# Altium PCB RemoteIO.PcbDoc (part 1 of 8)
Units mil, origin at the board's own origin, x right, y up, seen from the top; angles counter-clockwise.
Board outline 7874.02 x 2362.2 mil, 6 copper layers (Top Layer, GND1, Layer 2, PWR, GND2, Bottom Layer), stack 60.956 mil thick; 655 components, 447 nets, 2607 pads, 1444 vias.
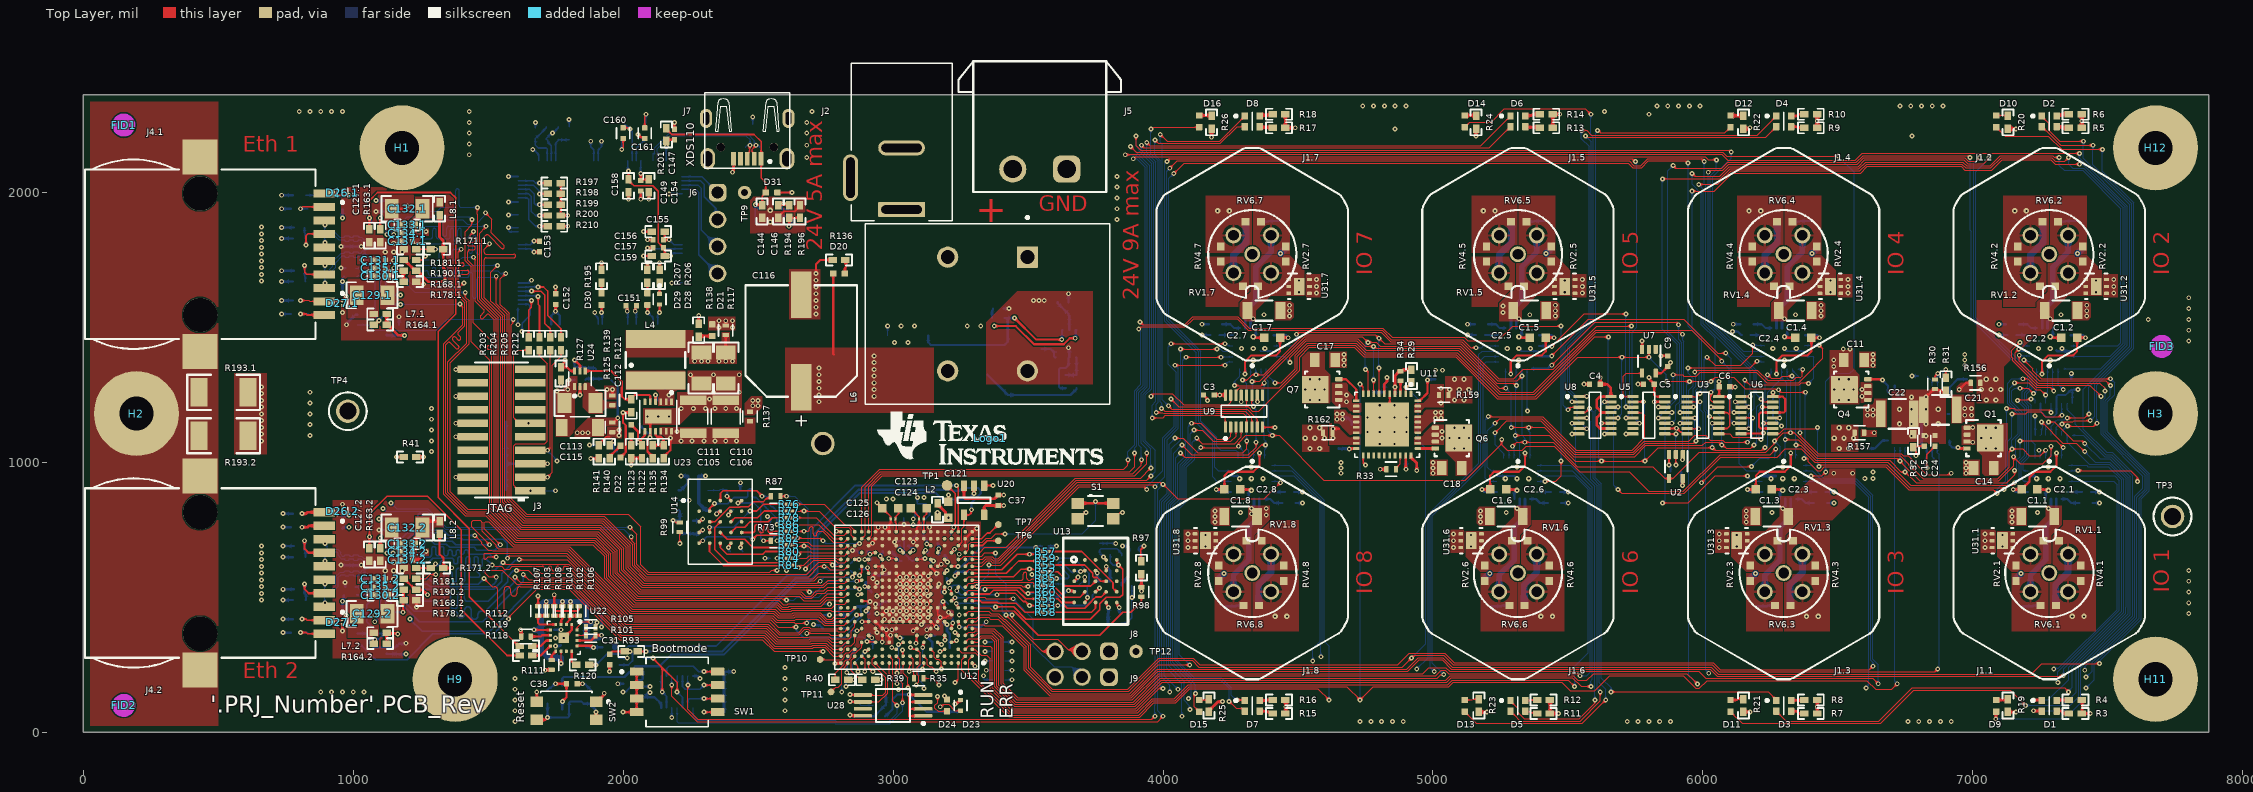
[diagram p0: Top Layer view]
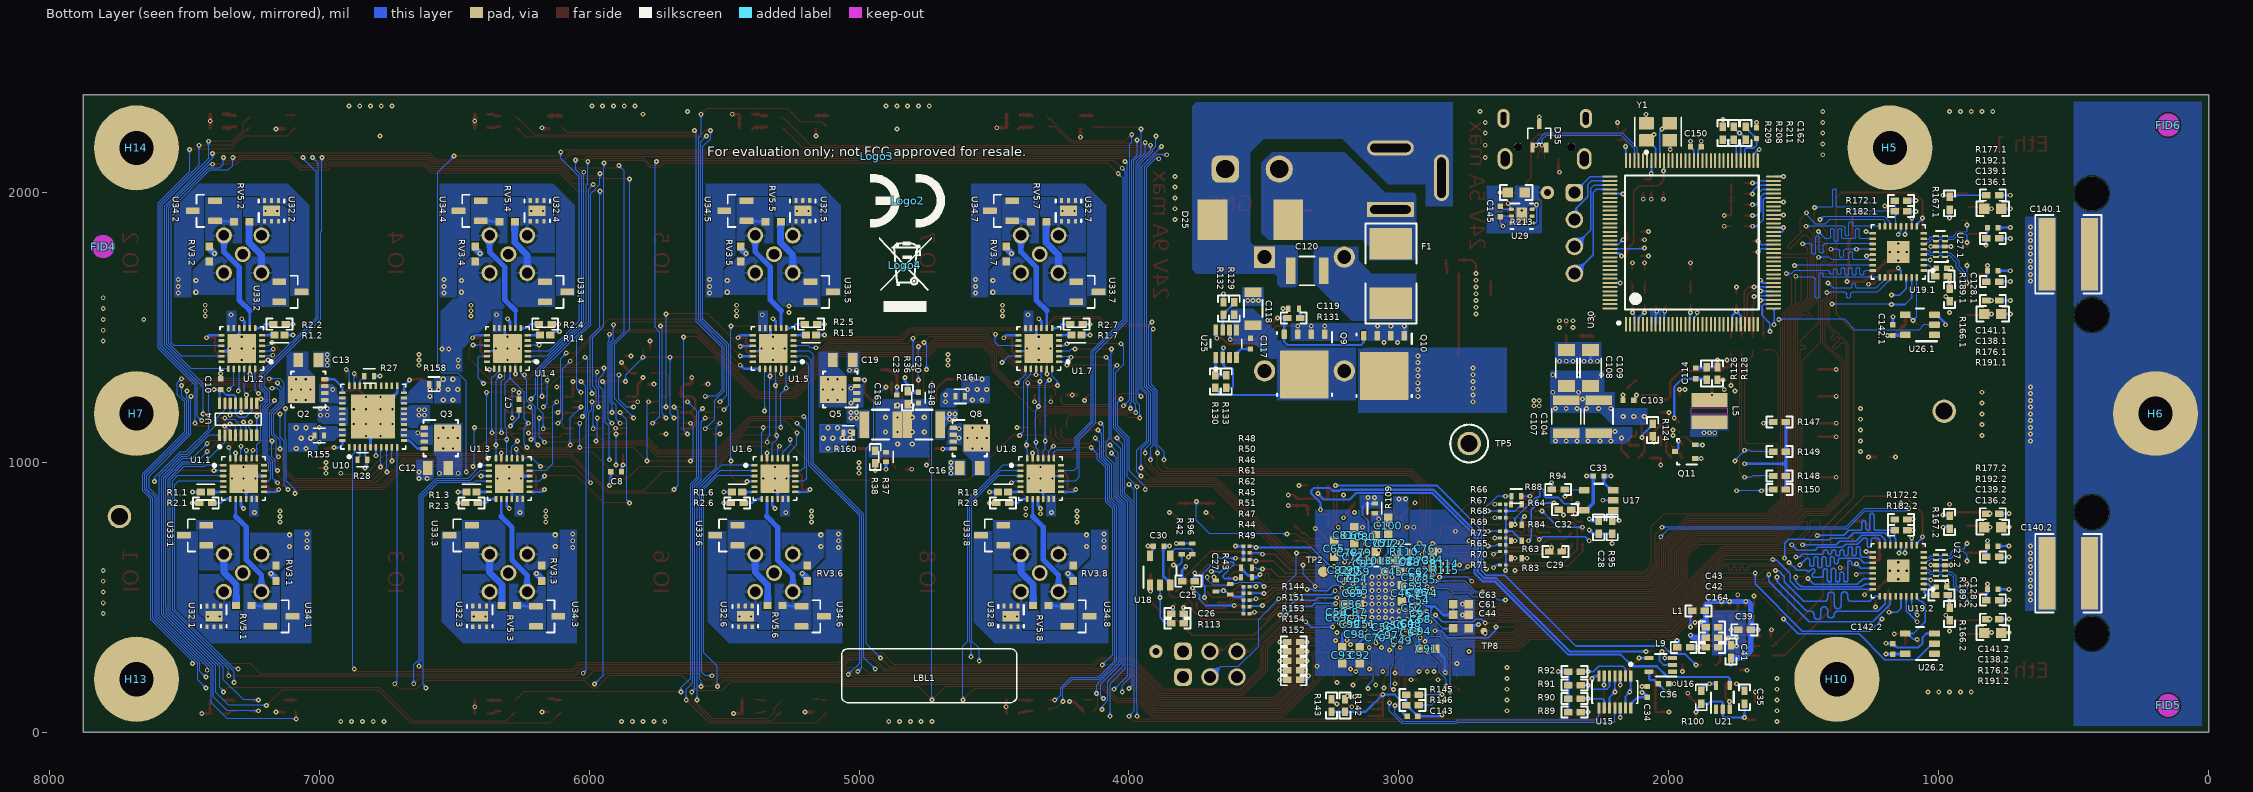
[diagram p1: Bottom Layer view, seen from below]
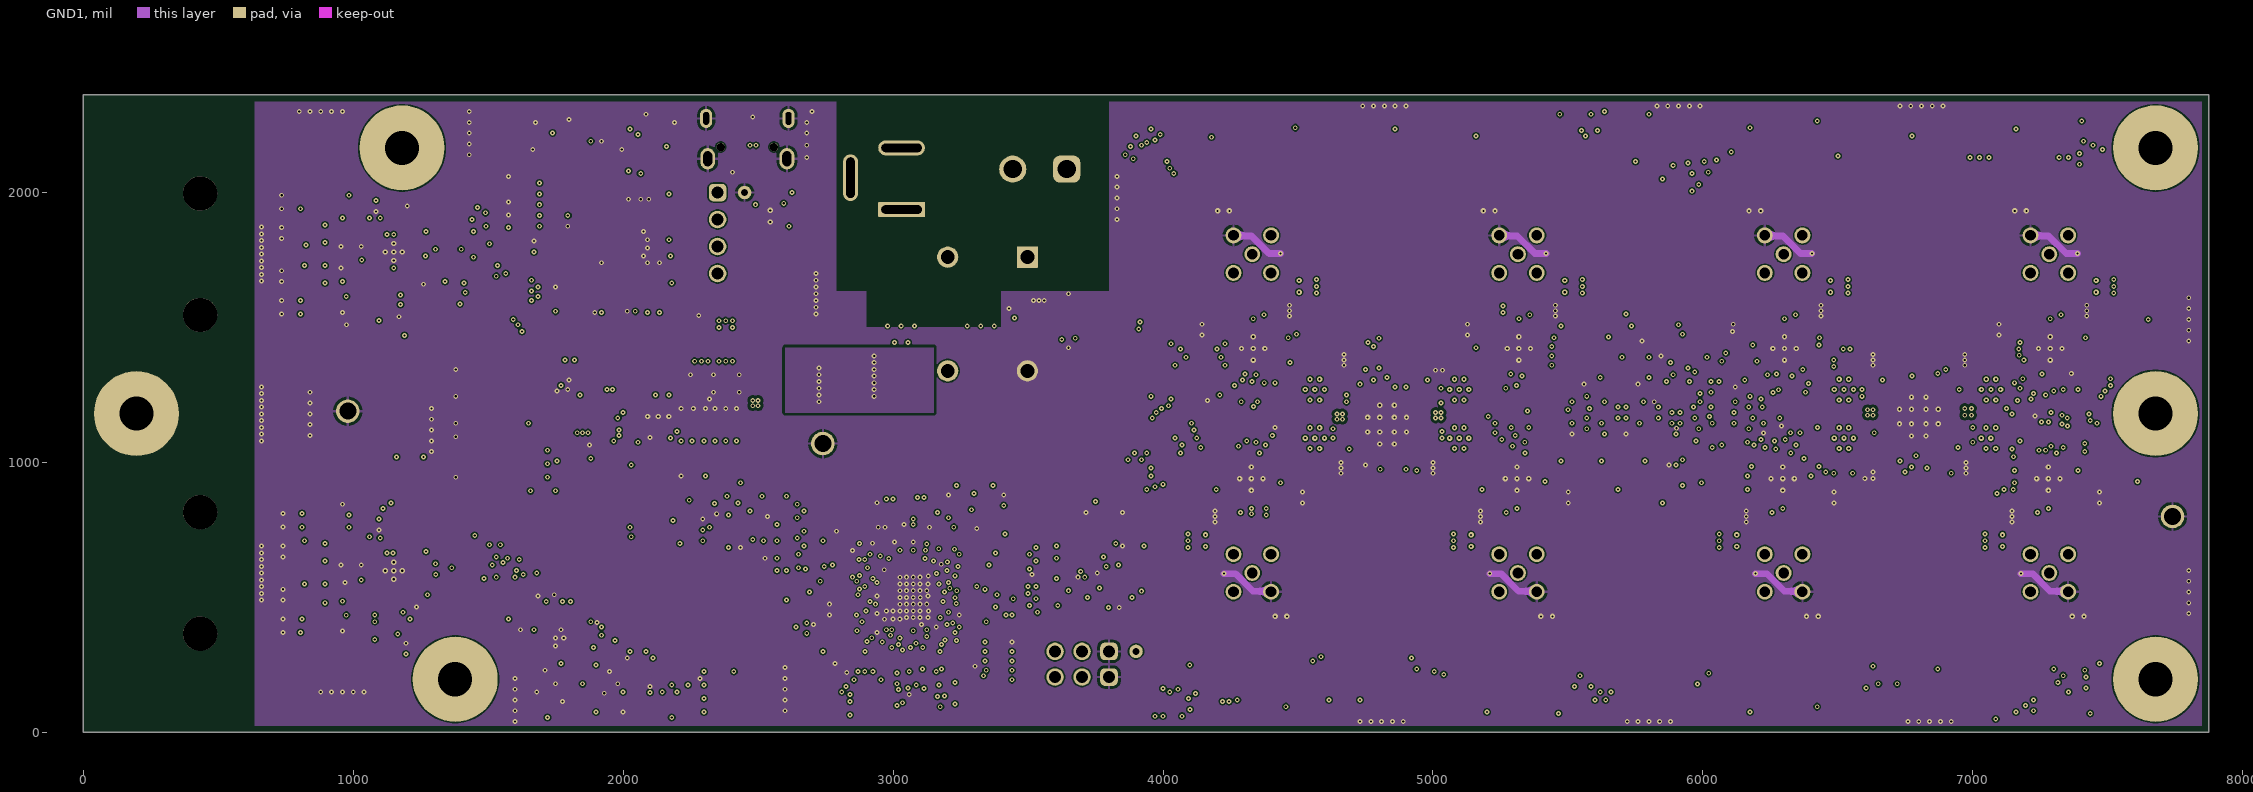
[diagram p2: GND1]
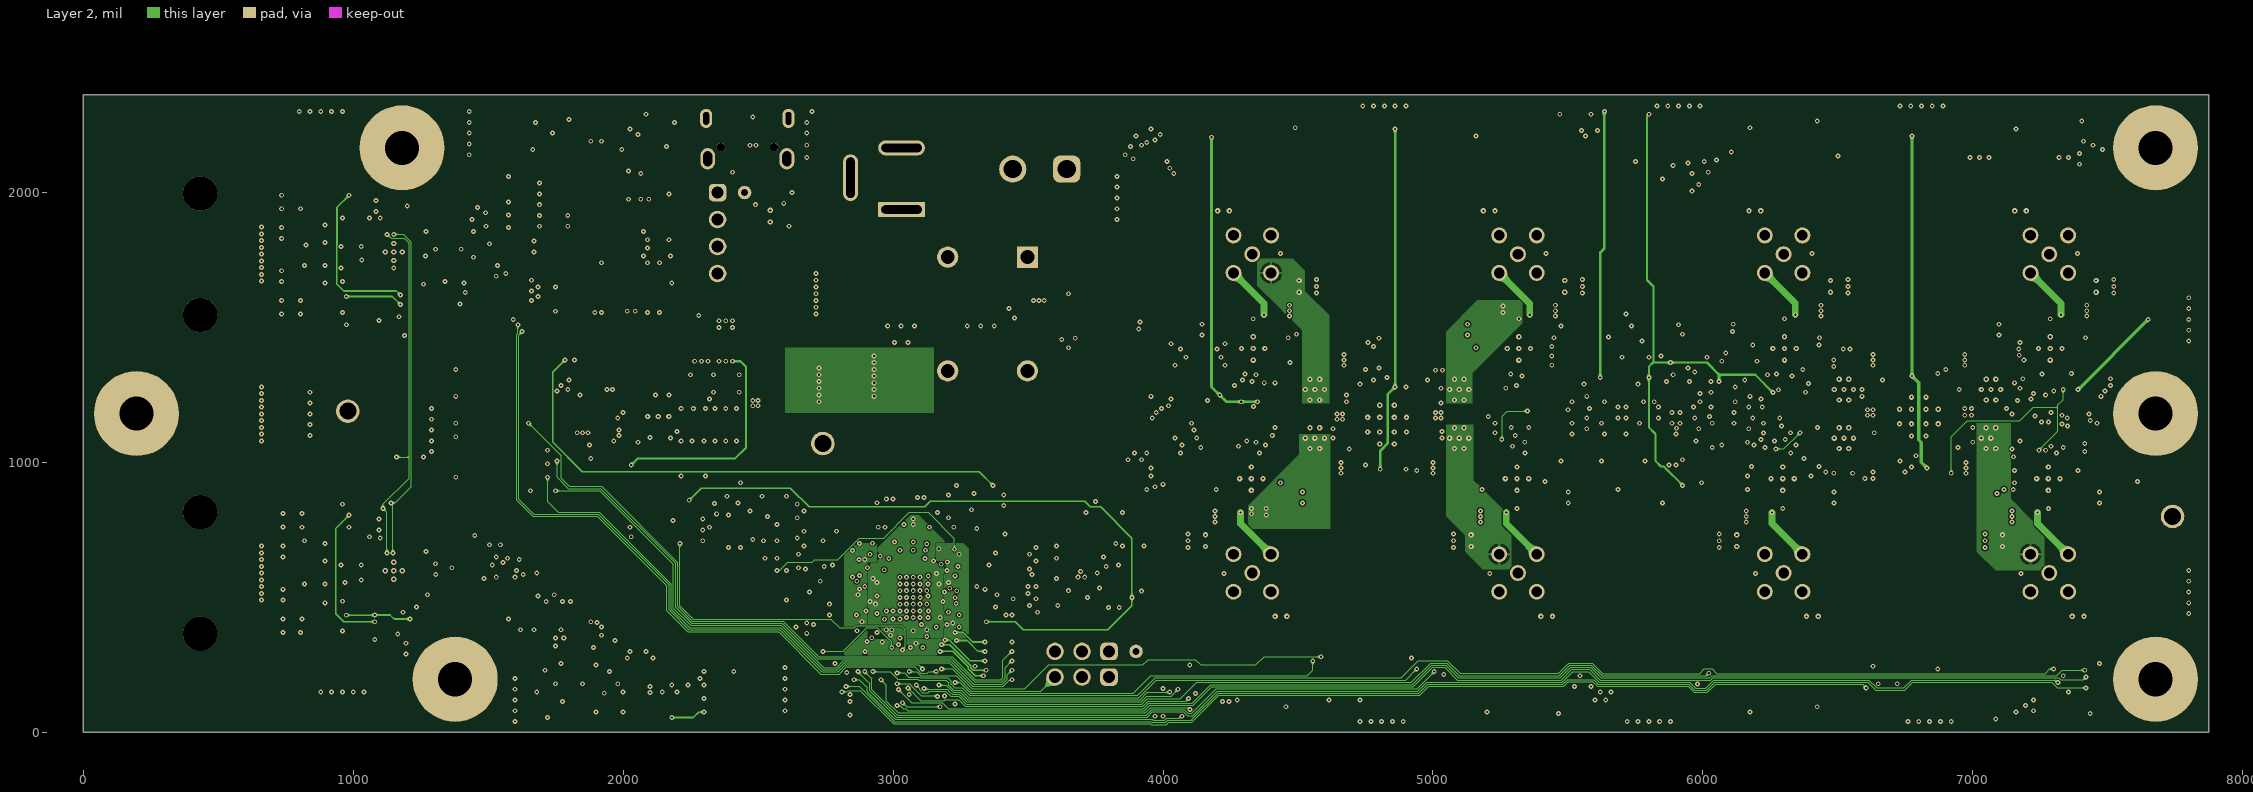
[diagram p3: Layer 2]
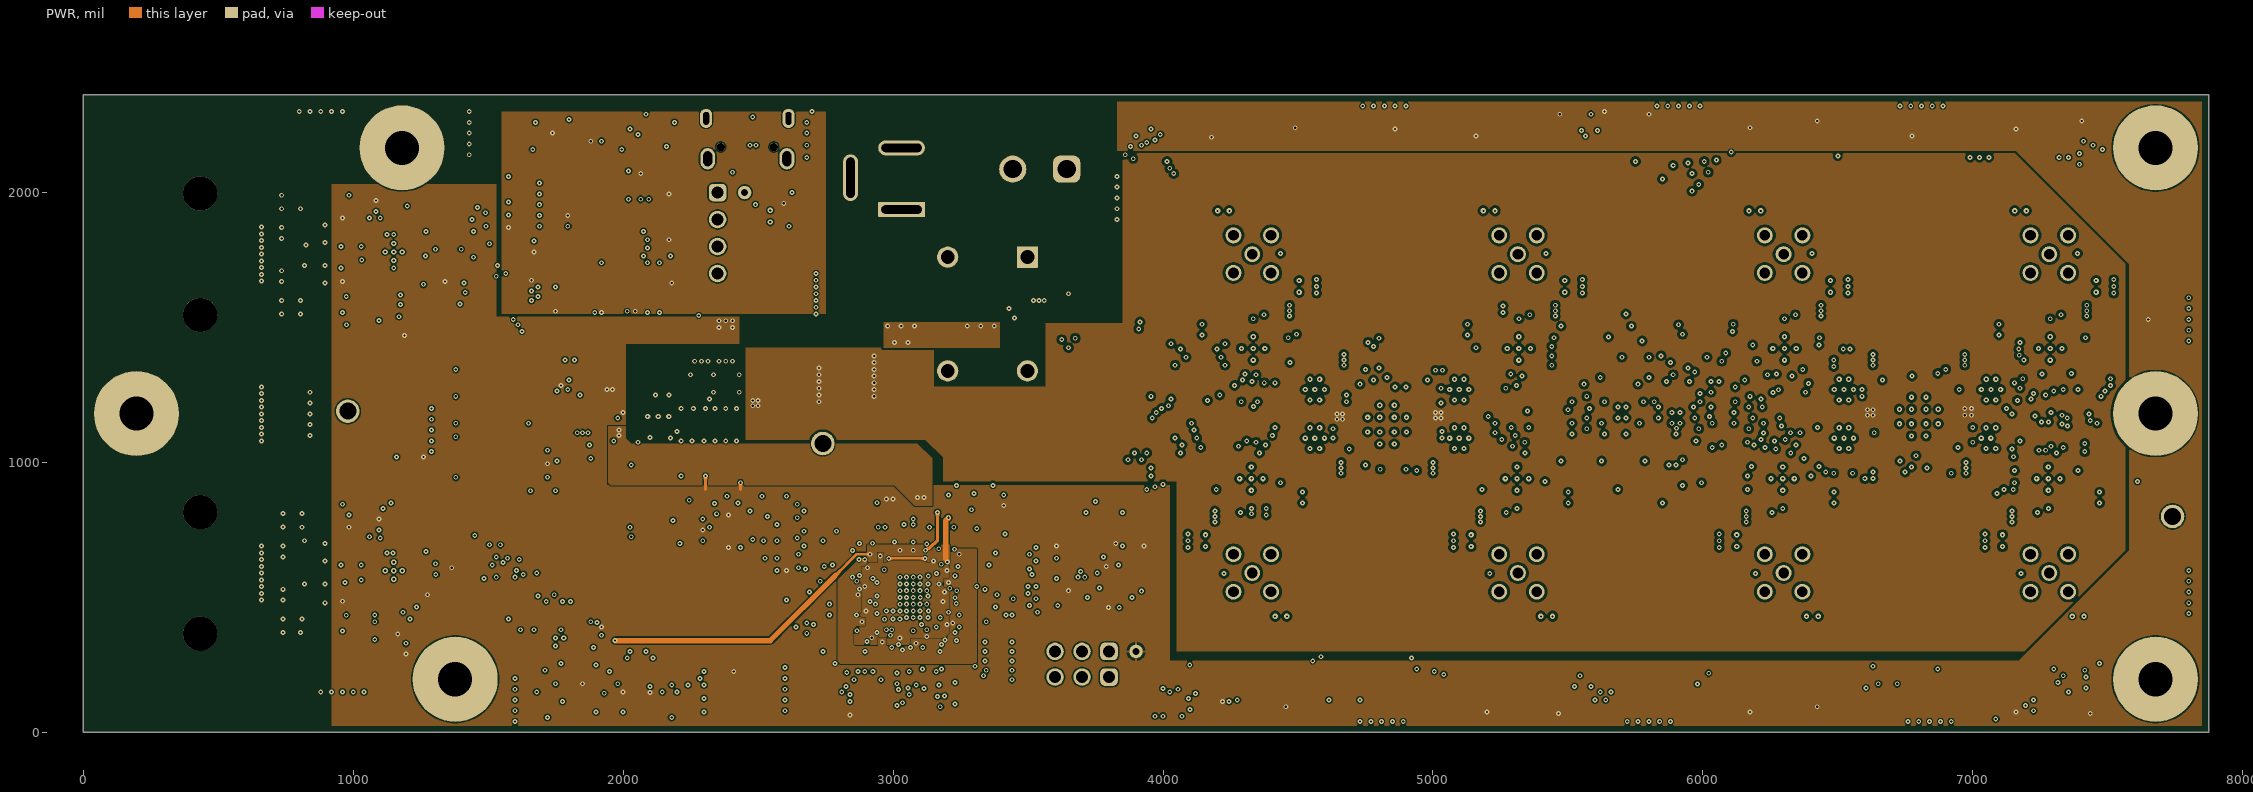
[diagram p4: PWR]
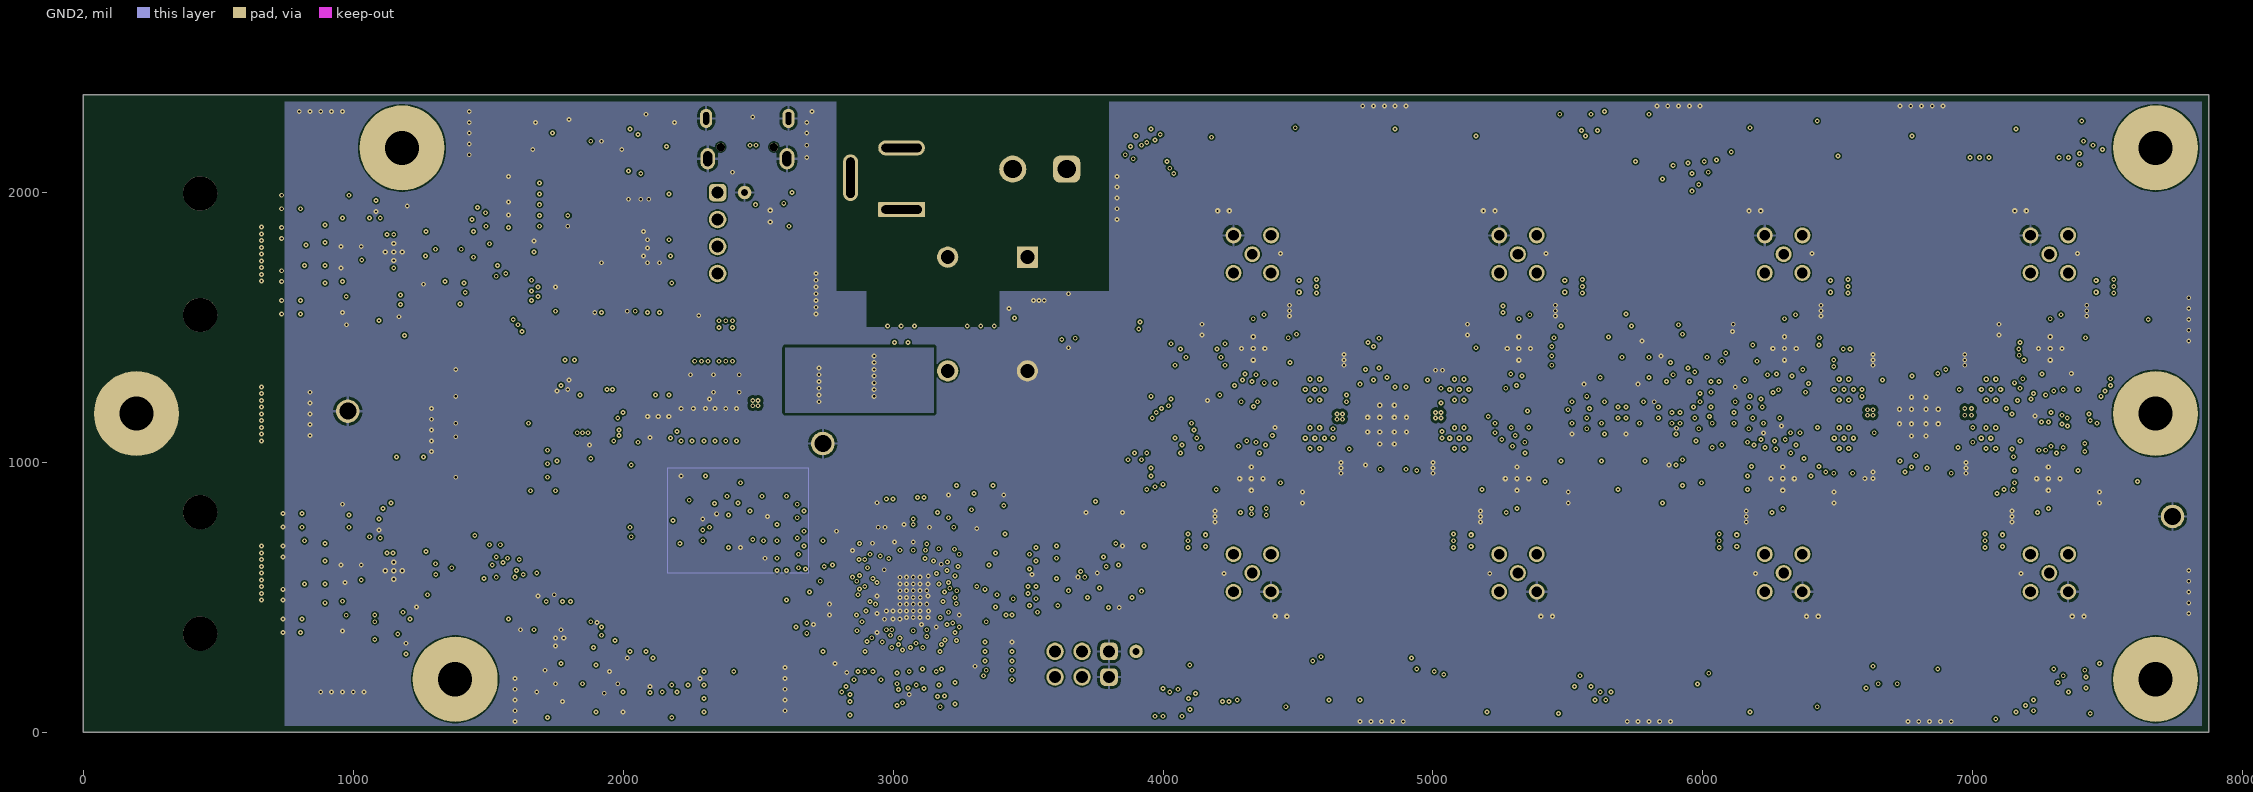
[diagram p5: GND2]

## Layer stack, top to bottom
Top Solder: solder mask 0.4, Solder Resist, Dk 3.5
Top Layer: signal copper 1.4
Dielectric 1: prepreg 3.91, PP-015, Dk 4.3
GND1: signal copper 0.689
Dielectric 2: core 21.65, Core-037, Dk 4.8
Layer 2: signal copper 0.689
Dielectric1: prepreg 4.28, PP-016, Dk 4.4
PWR: signal copper 0.689
Dielectric 3: core 21.65, Core-037, Dk 4.8
GND2: signal copper 0.689
Dielectric 4: prepreg 3.91, PP-015, Dk 4.3
Bottom Layer: signal copper 1.4
Bottom Solder: solder mask 0.4, Solder Resist, Dk 3.5

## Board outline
0,0 7874.02,0 7874.02,2362.2 0,2362.2

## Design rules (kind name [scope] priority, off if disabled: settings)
AcuteAngle [All] p1: minimum=4.50000000000000E+0001 checktracksonly=FALSE
AssemblyTestPointUsage [All] p1: valid=2
BoardOutlineClearance BoardOutlineClearance_MountingHoles [OnCopper and InComponentClass('Mounting Holes')] p1: gap=39.37 ignorepadtopadclearanceinfootprint=FALSE
BoardOutlineClearance BoardOutlineClearance_Poly [OnCopper and IsPoly] p2: gap=25 ignorepadtopadclearanceinfootprint=FALSE
BoardOutlineClearance [OnCopper and Not InComponentClass('Logo') and not InComponentClass('FiducialMark') and not InRegion(1000,500,4000,800) and not InPoly] p3: gap=20 ignorepadtopadclearanceinfootprint=FALSE
Clearance Clearance_24V [InNet('24V')] p1: gap=10 ignorepadtopadclearanceinfootprint=TRUE
Clearance Clearance_CPU [WithinRoom('CPU')] p2: gap=3.5 ignorepadtopadclearanceinfootprint=TRUE
Clearance Clearance_Keepouts [((IsTrack Or IsArc) And Not InPoly) And IsFree and IsKeepOut vs ((IsTrack Or IsArc) And Not InPoly) And IsFree and IsKeepOut] p3: gap=0 ignorepadtopadclearanceinfootprint=FALSE
Clearance Clearance_Poly [InPolygon] p4: gap=5 ignorepadtopadclearanceinfootprint=TRUE
Clearance Clearance_FiducialMark [IsKeepOut and InComponentClass('FiducialMark') vs IsPad and InComponentClass('FiducialMark')] p5: gap=0 ignorepadtopadclearanceinfootprint=FALSE
Clearance [All] p6: gap=4 ignorepadtopadclearanceinfootprint=TRUE
ComponentClearance ComponentClearance_J8J9 [InComponent('J8') or InComponent('J9')] p1: gap=0 collisioncheckmode=3 verticalgap=0 showdistances=FALSE
ComponentClearance ComponentClearance_MOV [InComponent('RV*') or InComponent('D32*') or InComponent('D33*') or InComponent('D34*')] p2: gap=0 collisioncheckmode=3 verticalgap=0 showdistances=FALSE
ComponentClearance ComponentClearance_MountingHoles_FiducialMarks [InComponentClass('Mounting Holes') vs InComponentClass('FiducialMark')] p3: gap=50 collisioncheckmode=3 verticalgap=10 showdistances=FALSE
ComponentClearance ComponentClearance_Shunt [InComponentClass('Header') vs InComponentClass('Shunt')] p4: gap=0 collisioncheckmode=3 verticalgap=0 showdistances=FALSE
ComponentClearance ComponentClearance_Logo [InComponentClass('Logo')] p5: gap=30 collisioncheckmode=3 verticalgap=10 showdistances=FALSE
ComponentClearance ComponentClearance_ScrewToNut [(HasFootprint('NY PMS 440 0025 PH')) vs (HasFootprint('Keystone_1902C'))] p6: gap=5 collisioncheckmode=3 verticalgap=10 showdistances=FALSE
ComponentClearance ComponentClearance_MountingHoles [InComponentClass('Mounting Holes')] p7: gap=39.37 collisioncheckmode=3 verticalgap=100000 showdistances=FALSE
ComponentClearance ComponentClearance_SmallPassives [HasFootprint('*0201*') or HasFootprint('*0402*') or HasFootprint('0508') or HasFootprint('*0603*') or HasFootprint('0612') or HasFootprint('0805*') or HasFootprint('0815*') or HasFootprint('0830*') or HasFootprint('1206*') or HasFootprint('1210*') or HasFootprint('1808*') or HasFootprint('1812*') or HasFootprint('1825*') or HasFootprint('2010*') or HasFootprint('2220*') or HasFootprint('2225*') or HasFootprint('2512*') or HasFootprint('2728*') or HasFootprint('3518*') or HasFootprint('*DQA*') vs HasFootprint('*0201*') or HasFootprint('*0402*') or HasFootprint('0508') or HasFootprint('*0603*') or HasFootprint('0612') or HasFootprint('0805*') or HasFootprint('0815*') or HasFootprint('0830*') or HasFootprint('1206*') or HasFootprint('1210*') or HasFootprint('1808*') or HasFootprint('1812*') or HasFootprint('1825*') or HasFootprint('2010*') or HasFootprint('2220*') or HasFootprint('2225*') or HasFootprint('2512*') or HasFootprint('2728*') or HasFootprint('3518*') or HasFootprint('*DQA*')] p8: gap=7.87 collisioncheckmode=3 verticalgap=10 showdistances=FALSE
ComponentClearance ComponentClearance_THtoSMT [IsThruComponent vs IsSMTComponent] p9: gap=30 collisioncheckmode=3 verticalgap=30 showdistances=FALSE
ComponentClearance ComponentClearance_THtoTH [IsThruComponent vs IsThruComponent] p10: gap=20 collisioncheckmode=3 verticalgap=30 showdistances=FALSE
ComponentClearance [All] p11: gap=20 collisioncheckmode=3 verticalgap=10 showdistances=FALSE
DiffPairsRouting DiffPairsRouting_D100 [InDifferentialPairClass('All Differential Pairs')] p1: maxlimit=5 minlimit=5 mostfreqgap=5 toplayer_minwidth=4.32 toplayer_maxwidth=4.32 toplayer_prefwidth=4.32 midlayer1_minwidth=2.83 midlayer1_maxwidth=2.83 midlayer1_prefwidth=2.83 midlayer2_minwidth=2.87 midlayer2_maxwidth=2.87 midlayer2_prefwidth=2.87 midlayer3_minwidth=2.87 midlayer3_maxwidth=2.87 midlayer3_prefwidth=2.87 midlayer4_minwidth=2.83 midlayer4_maxwidth=2.83 midlayer4_prefwidth=2.83 bottomlayer_minwidth=4.32 bottomlayer_maxwidth=4.32 bottomlayer_prefwidth=4.32 impedanceprofiledriven=TRUE impedanceprofileid={3DAFA0DE-273E-4892-9D57-D61B4A4269A0} impedanceprofilevalue=100.000000 maxuncoupledlength=500
DiffPairsRouting DiffPairsRouting_D90 [InDifferentialPairClass('D90')] p2: maxlimit=5 minlimit=5 mostfreqgap=5 toplayer_minwidth=5.61 toplayer_maxwidth=5.61 toplayer_prefwidth=5.61 midlayer1_minwidth=3.83 midlayer1_maxwidth=3.83 midlayer1_prefwidth=3.83 midlayer2_minwidth=3.93 midlayer2_maxwidth=3.93 midlayer2_prefwidth=3.93 midlayer3_minwidth=3.93 midlayer3_maxwidth=3.93 midlayer3_prefwidth=3.93 midlayer4_minwidth=3.83 midlayer4_maxwidth=3.83 midlayer4_prefwidth=3.83 bottomlayer_minwidth=5.61 bottomlayer_maxwidth=5.61 bottomlayer_prefwidth=5.61 impedanceprofiledriven=TRUE impedanceprofileid={56A04E09-FE34-4AAD-9D23-3BAA67225C0C} impedanceprofilevalue=90.000000 maxuncoupledlength=500
DiffPairsRouting [All] p3: maxlimit=100 minlimit=10 mostfreqgap=10 toplayer_minwidth=15 toplayer_maxwidth=15 toplayer_prefwidth=15 midlayer1_minwidth=15 midlayer1_maxwidth=15 midlayer1_prefwidth=15 midlayer2_minwidth=15 midlayer2_maxwidth=15 midlayer2_prefwidth=15 midlayer3_minwidth=15 midlayer3_maxwidth=15 midlayer3_prefwidth=15 midlayer4_minwidth=15 midlayer4_maxwidth=15 midlayer4_prefwidth=15 bottomlayer_minwidth=15 bottomlayer_maxwidth=15 bottomlayer_prefwidth=15 maxuncoupledlength=1000
FabricationTestPointUsage TestPointUsage [All] p1: valid=2 allowmultiple=FALSE
FabricationTestpoint Testpoint [All] p1: side=3 testpointundercomponent=TRUE minsize=40 maxsize=100 preferedsize=60 minholesize=0 maxholesize=40 preferedholesize=32 testpointgrid=1 allowsidetop=TRUE allowsidebottom=TRUE usegrid=TRUE gridtolerance=0.01
FanoutControl Fanout_LCC [IsLCC] p1: bgadir=Out bgaviamode=Centered fanoutstyle=Auto fanoutdirection=Alternating viagrid=1 // Fanout_LCC (Default Rule)
FanoutControl Fanout_BGA [IsBGA] p2: bgadir=Out bgaviamode=Centered fanoutstyle=Auto fanoutdirection=Alternating viagrid=1 // Fanout_BGA (Default Rule)
FanoutControl Fanout_Default [All] p4: bgadir=Out bgaviamode=Centered fanoutstyle=Auto fanoutdirection=Alternating viagrid=1 // Fanout_Default (Default Rule)
FanoutControl Fanout_Small [(CompPinCount < 5)] p5: bgadir=Out bgaviamode=Centered fanoutstyle=Auto fanoutdirection=OutThenIn viagrid=1 // Fanout_Small (Default Rule)
HoleSize [All] p1: absolutevalues=TRUE maxlimit=251 minlimit=7.87 maxpercent=80.000 minpercent=20.000
MatchedLengths MatchLengths_xSignals_U14_U12 [InxSignalClass('xSignals_U14_U12_MatchLengthsClass')] p1: tolerance=50 checknetsindiffpair=FALSE checkdiffpairvsdiffpair=TRUE checkxsignals=TRUE checkothers=TRUE usedelayunits=TRUE delaytolerance=30.000000 targetsourcename=OSPI1_CLK-NetR86_2_PP1
MatchedLengths MatchLengths_xSignals_U19.1_U12_tx [InxSignalClass('xSignals_U19.1_U12_MatchLengthsClass_tx')] p2: tolerance=50 checknetsindiffpair=FALSE checkdiffpairvsdiffpair=TRUE checkxsignals=TRUE checkothers=TRUE
MatchedLengths MatchLengths_xSignals_U19.1_U12 [InxSignalClass('xSignals_U19.1_U12_MatchLengthsClass_rx')] p3: tolerance=50 checknetsindiffpair=FALSE checkdiffpairvsdiffpair=TRUE checkxsignals=TRUE checkothers=TRUE
MatchedLengths MatchLengths_xSignals_U13_U12 [InxSignalClass('xSignals_U13_U12_MatchLengthsClass')] p4: tolerance=50 checknetsindiffpair=FALSE checkdiffpairvsdiffpair=TRUE checkxsignals=TRUE checkothers=TRUE usedelayunits=TRUE delaytolerance=30.000000 targetsourcename=OSPI0_CLK-NetR85_2_PP2
MatchedLengths MatchLengths_xSignals_U19.2_U12_TX [InxSignalClass('xSignals_U19.2_U12_MatchLengthsClass_tx')] p5: tolerance=50 checknetsindiffpair=FALSE checkdiffpairvsdiffpair=TRUE checkxsignals=TRUE checkothers=TRUE
MatchedLengths MatchLengths_xSignals_U19.2_U12_RX [InxSignalClass('xSignals_U19.2_U12_MatchLengthsClass_rx')] p6: tolerance=50 checknetsindiffpair=FALSE checkdiffpairvsdiffpair=TRUE checkxsignals=TRUE checkothers=TRUE
MinimumAnnularRing MinimumAnnularRing_ThermalPadVias [IsVia and InAnyComponent] p1: minimumring=5.91
MinimumAnnularRing [All] p2: minimumring=4.9
MinimumSolderMaskSliver MinimumSolderMaskSliver_Logo [InComponentClass('Logo') vs InComponentClass('Logo')] p1: minsoldermaskwidth=0.7
MinimumSolderMaskSliver [All] p2: minsoldermaskwidth=2
PlaneConnect [All] p1: planeconnectstyle=Relief reliefexpansion=10 reliefentries=4 reliefconductorwidth=10 reliefairgap=10
PolygonConnect PolygonConnect_Power [InNetClass('PWR')  or InComponent('L6') or InComponent('Q10') or InComponent('C116')] p1: connectstyle=Direct reliefconductorwidth=10 reliefentries=4 polygonreliefangle="90 Angle" airgapwidth=10
PolygonConnect PolygonConnect_SMD [IsVia or HasFootprint('*0402*') or HasFootprint('*0201*') or HasFootprint('*0603*') or HasFootprint('*0805*') or HasFootprint('*1206*') or HasFootprint('*1210*') or HasFootprint('*ZFG*') or HasFootprint('*DRR*') or HasFootprint('*MAPI*') or HasFootprint('*1825*') or HasFootprint('*DRL*') or HasFootprint('*DBZ*') or HasFootprint('*DRV*') or HasFootprint('*RGE*') or HasFootprint('*DNH*') or HasFootprint('*RHA*') or HasFootprint('*DQJ*') or HasFootprint('*2010*') or HasFootprint('7498011211') or HasFootprint('*PMS*')] p2: connectstyle=Direct reliefconductorwidth=10 reliefentries=4 polygonreliefangle="90 Angle" airgapwidth=10
PolygonConnect [All] p3: connectstyle=Relief reliefconductorwidth=10 reliefentries=4 polygonreliefangle="90 Angle" airgapwidth=10
RoomDefinition CPU [False vs False] p1: confinementstyle=ConfineIn formatcopy=TRUE lockcomponents=FALSE outline 2785,760 3310,760 3310,240 2785,240
RoomDefinition Eth2 [InComponentClass('Eth2')] p2: confinementstyle=ConfineIn formatcopy=TRUE lockcomponents=FALSE outline 0,1181.1 1377.95,1181.1 1377.95,0 0,0
RoomDefinition IO2 [InComponentClass('IO2')] p3: confinementstyle=ConfineIn formatcopy=TRUE lockcomponents=FALSE outline 7637.8,1299.21 6929.13,1299.21 6929.13,2165.35 7637.8,2165.35
RoomDefinition IO1 [InComponentClass('IO1')] p4: confinementstyle=ConfineIn formatcopy=TRUE lockcomponents=FALSE outline 6929.13,1062.99 7637.8,1062.99 7637.8,196.85 6929.13,196.85
RoomDefinition IO8 [InComponentClass('IO8')] p5: confinementstyle=ConfineIn formatcopy=TRUE lockcomponents=FALSE outline 3976.38,1062.99 4685.04,1062.99 4685.04,196.85 3976.38,196.85
RoomDefinition IO4 [InComponentClass('IO4')] p6: confinementstyle=ConfineIn formatcopy=TRUE lockcomponents=FALSE outline 6653.54,1299.21 5944.88,1299.21 5944.88,2165.35 6653.54,2165.35
RoomDefinition Eth1 [InComponentClass('Eth1')] p7: confinementstyle=ConfineIn formatcopy=TRUE lockcomponents=FALSE outline 0,2362.2 1377.95,2362.2 1377.95,1181.1 0,1181.1
RoomDefinition IO3 [InComponentClass('IO3')] p8: confinementstyle=ConfineIn formatcopy=TRUE lockcomponents=FALSE outline 5944.88,1062.99 6653.54,1062.99 6653.54,196.85 5944.88,196.85
RoomDefinition IO5 [InComponentClass('IO5')] p9: confinementstyle=ConfineIn formatcopy=TRUE lockcomponents=FALSE outline 5669.29,1299.21 4960.63,1299.21 4960.63,2165.35 5669.29,2165.35
RoomDefinition IO6 [InComponentClass('IO6')] p10: confinementstyle=ConfineIn formatcopy=TRUE lockcomponents=FALSE outline 4960.63,1062.99 5669.29,1062.99 5669.29,196.85 4960.63,196.85
RoomDefinition IO7 [InComponentClass('IO7')] p11: confinementstyle=ConfineIn formatcopy=TRUE lockcomponents=FALSE outline 4685.04,1299.21 3976.38,1299.21 3976.38,2165.35 4685.04,2165.35
RoutingVias ThermalPadVias [IsVia and InAnyComponent] p1: holewidth=7.87 width=19.68 viastyle="Through Hole" minholewidth=7.87 minwidth=19.68 maxholewidth=12.99 maxwidth=23.62
RoutingVias [All] p2: holewidth=8 width=18 viastyle="Through Hole" minholewidth=8 minwidth=18 maxholewidth=40 maxwidth=65
SignalStimulus "Schematic Signal Stimulus" [All] p1: kind=2 level=0 starttime=0.000 stoptime=4.000u periodtime=8.000u
SilkToBoardRegionClearance [Not ((IsComment or IsDesignator) And (Hide <> 'False')) and not InRegion(1000,500,4000,800)] p1:
SilkToSilkClearance SilkToSilkClearance_Pb-FreeLogo [(HasFootprint('Pb-Free_Overlay_Medium') OR HasFootprint('Pb-Free_Overlay_Small')) vs (HasFootprint('Pb-Free_Overlay_Medium') OR HasFootprint('Pb-Free_Overlay_Small'))] p1: silktosilkclearance=0
SilkToSilkClearance [All] p2: silktosilkclearance=2
SilkToSolderMaskClearance SilkToComponentPadClearance [(IsPad or IsFill or IsRegion) and InAnycomponent] p1: minsilkscreentomaskgap=4 clearancetoexposedcopper=TRUE
SilkToSolderMaskClearance "Silk to Solder Mask Opening" [All] p2: minsilkscreentomaskgap=3.94 clearancetoexposedcopper=FALSE
SolderMaskExpansion [All] p1: expansion=1.97 istentingtop=FALSE
SupplyNets "Schematic Supply Nets_8" [InNet('3V3')] p1: voltage=3.300
SupplyNets "Schematic Supply Nets_7" [InNet('1V25')] p2: voltage=1.250
SupplyNets "Schematic Supply Nets_4" [InNet('EARTH')] p3: voltage=0.000
SupplyNets "Schematic Supply Nets_6" [InNet('+5V0_USB')] p4: voltage=0.000
SupplyNets "Schematic Supply Nets_5" [InNet('+3V3_XDS110')] p5: voltage=0.000
SupplyNets "Schematic Supply Nets_3" [InNet('GND')] p6: voltage=0.000
SupplyNets "Schematic Supply Nets_2" [InNet('24V')] p7: voltage=0.000
UnRoutedNet [All] p1: checkbadconnections=TRUE
Width Width_50Ohm [InNetClass('S50')] p1: maxlimit=6.45 minlimit=4.69 preferedwidth=5 toplayer_minwidth=6.45 toplayer_prefwidth=6.45 midlayer1_maxwidth=4.69 midlayer1_prefwidth=4.69 midlayer2_minwidth=5 midlayer2_maxwidth=5 midlayer3_minwidth=5 midlayer3_maxwidth=5 midlayer4_maxwidth=4.69 midlayer4_prefwidth=4.69 bottomlayer_minwidth=6.45 bottomlayer_prefwidth=6.45 impedanceprofiledriven=TRUE impedanceprofileid={59106AC3-4B15-4899-84D9-F4FDE36C6D91} impedanceprofilevalue=50.000000 minimp=50.000000 maximp=50.000000 favimp=50.000000
Width Width_CPU [WithinRoom('CPU')] p2: maxlimit=50 minlimit=3.5 preferedwidth=4
Width [All] p3: maxlimit=100 minlimit=4 preferedwidth=6 checkconnectedcopper=TRUE
14 further rules are at their usual default settings.

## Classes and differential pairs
net class PWR: NetC117_2 NetC120_1 NetC120_2 NetD25_2
differential pair class D100: RD.1 RD.2 TD.1 TD.2
net class S50: 25MHz.1 25MHz.2 NetR120_2
net class MII_TX: MII1_TXCLK MII1_TXD0 MII1_TXD1 MII1_TXD2 MII1_TXD3 MII1_TXEN MII2_TXCLK MII2_TXD0 MII2_TXD1 MII2_TXD2 MII2_TXD3 MII2_TXEN
net class MII_RX: MII1_RX_ER MII1_RXCLK MII1_RXD0 MII1_RXD1 MII1_RXD2 MII1_RXD3 MII1_RXDV MII2_RX_ER MII2_RXCLK MII2_RXD0 MII2_RXD1 MII2_RXD2 MII2_RXD3 MII2_RXDV
differential pair class D90: USB
component class Debug: C144 C145 C146 C147 C149 C150 C151 C152 C153 C154 C155 C156 C157 C158 C159 C160 C161 C162 D28 D29 D30 D31 D35 J6 J7 R194 R195 R196 R197 R198 R199 R200 R201 R203 R204 R205 R206 R207 R208 R209 R210 R211 R212 R213 TP9 U29 U30 Y1
channel class RemoteIO_IOLinkPort: IO1 IO2 IO3 IO4 IO5 IO6 IO7 IO8
channel class RemoteIO_Ethernet: Eth1 Eth2
net class LED[1..24]: LED1 LED2 LED3 LED4 LED5 LED6 LED7 LED8 LED9 LED10 LED11 LED12 LED13 LED14 LED15 LED16 LED17 LED18 LED19 LED20 LED21 LED22 LED23 LED24
net class L+[1..8]: L+1 L+2 L+3 L+4 L+5 L+6 L+7 L+8
net class IO_TX[1..8]: IO_TX1 IO_TX2 IO_TX3 IO_TX4 IO_TX5 IO_TX6 IO_TX7 IO_TX8
net class IO_RX[1..8]: IO_RX1 IO_RX2 IO_RX3 IO_RX4 IO_RX5 IO_RX6 IO_RX7 IO_RX8
net class IO_EN[1..8]: IO_EN1 IO_EN2 IO_EN3 IO_EN4 IO_EN5 IO_EN6 IO_EN7 IO_EN8
net class DIO_TX[1..8]: DIO_TX1 DIO_TX2 DIO_TX3 DIO_TX4 DIO_TX5 DIO_TX6 DIO_TX7 DIO_TX8
net class DIO_RX[1..8]: DIO_RX1 DIO_RX2 DIO_RX3 DIO_RX4 DIO_RX5 DIO_RX6 DIO_RX7 DIO_RX8
net class DIO_EN[1..8]: DIO_EN1 DIO_EN2 DIO_EN3 DIO_EN4 DIO_EN5 DIO_EN6 DIO_EN7 DIO_EN8
net class CS[1..8]: CS1 CS2 CS3 CS4 CS5 CS6 CS7 CS8
component class SOP: C31 C34 C36 R89 R90 R91 R92 R93 SW1 U15 U16
component class RAM: C28 C29 C32 C33 R63 R64 R65 R66 R67 R68 R69 R70 R71 R72 R73 R74 R75 R76 R77 R78 R79 R80 R81 R82 R83 R84 R87 R88 R94 R95 U14 U17
component class Power: C103 C104 C105 C106 C107 C108 C109 C110 C111 C112 C113 C114 C115 C116 C117 C118 C119 C120 D20 D21 D22 D25 F1 J2 J5 L4 L5 L6 Q9 Q10 Q11 R117 R121 R122 R123 R124 R125 R126 R127 R128 R129 R130 R131 R132 R133 R134 R135 R136 R137 R138 R139 R140 R141 U23 U24 U25
component class IOs: C3 C4 C5 C6 C7 C8 C9 C10 D1 D2 D3 D4 D5 D6 D7 D8 D9 D10 D11 D12 D13 D14 D15 D16 R3 R4 R5 R6 R7 R8 R9 R10 R11 R12 R13 R14 R15 R16 R17 R18 R19 R20 R21 R22 R23 R24 R25 R26 U2 U3 U4 U5 U6 U7 U8 U9
component class IO8: C1.8 C2.8 J1.8 R1.8 R2.8 RV1.8 RV2.8 RV3.8 RV4.8 RV5.8 RV6.8 U1.8 U31.8 U32.8 U33.8 U34.8
component class IO7: C1.7 C2.7 J1.7 R1.7 R2.7 RV1.7 RV2.7 RV3.7 RV4.7 RV5.7 RV6.7 U1.7 U31.7 U32.7 U33.7 U34.7
component class IO6: C1.6 C2.6 J1.6 R1.6 R2.6 RV1.6 RV2.6 RV3.6 RV4.6 RV5.6 RV6.6 U1.6 U31.6 U32.6 U33.6 U34.6
component class IO5: C1.5 C2.5 J1.5 R1.5 R2.5 RV1.5 RV2.5 RV3.5 RV4.5 RV5.5 RV6.5 U1.5 U31.5 U32.5 U33.5 U34.5
component class IO4: C1.4 C2.4 J1.4 R1.4 R2.4 RV1.4 RV2.4 RV3.4 RV4.4 RV5.4 RV6.4 U1.4 U31.4 U32.4 U33.4 U34.4
component class IO3: C1.3 C2.3 J1.3 R1.3 R2.3 RV1.3 RV2.3 RV3.3 RV4.3 RV5.3 RV6.3 U1.3 U31.3 U32.3 U33.3 U34.3
component class IO2: C1.2 C2.2 J1.2 R1.2 R2.2 RV1.2 RV2.2 RV3.2 RV4.2 RV5.2 RV6.2 U1.2 U31.2 U32.2 U33.2 U34.2
component class IO1: C1.1 C2.1 J1.1 R1.1 R2.1 RV1.1 RV2.1 RV3.1 RV4.1 RV5.1 RV6.1 U1.1 U31.1 U32.1 U33.1 U34.1
component class HSS: C11 C12 C13 C14 C15 C16 C17 C18 C19 C20 C21 C22 C23 C24 C148 C163 Q1 Q2 Q3 Q4 Q5 Q6 Q7 Q8 R27 R28 R29 R30 R31 R32 R33 R34 R36 R37 R38 R155 R156 R157 R158 R159 R160 R161 R162 U10 U11
component class Header: J3 J6 J8 J9
component class Flash: C25 C26 C27 C30 R42 R43 R44 R45 R46 R47 R48 R49 R50 R51 R52 R53 R54 R55 R56 R57 R58 R59 R60 R61 R62 R96 R97 U13 U18
component class Eth2: C127.2 C128.2 C129.2 C130.2 C131.2 C132.2 C133.2 C134.2 C135.2 C136.2 C137.2 C138.2 C139.2 C140.2 C141.2 C142.2 D26.2 D27.2 J4.2 L7.2 L8.2 R163.2 R164.2 R166.2 R167.2 R168.2 R171.2 R172.2 R176.2 R177.2 R178.2 R181.2 R182.2 R189.2 R190.2 R191.2 R192.2 R193.2 U19.2 U26.2 U27.2
component class Eth1: C127.1 C128.1 C129.1 C130.1 C131.1 C132.1 C133.1 C134.1 C135.1 C136.1 C137.1 C138.1 C139.1 C140.1 C141.1 C142.1 D26.1 D27.1 J4.1 L7.1 L8.1 R163.1 R164.1 R166.1 R167.1 R168.1 R171.1 R172.1 R176.1 R177.1 R178.1 R181.1 R182.1 R189.1 R190.1 R191.1 R192.1 R193.1 U19.1 U26.1 U27.1
component class CPU_PWR_CLK_RST: C35 C37 C38 C39 C41 C42 C43 C44 C45 C46 C47 C48 C49 C50 C51 C52 C53 C54 C55 C56 C57 C58 C59 C60 C61 C62 C63 C64 C65 C66 C67 C68 C69 C70 C71 C72 C73 C74 C75 C76 C77 C78 C79 C80 C81 C82 C83 C84 C85 C86 C87 C88 C89 C90 C91 C92 C93 C94 C95 C96 C97 C98 C99 C100 C101 C102 C121 C122 C164 L1 L2 L3 L9 R100 R101 R102 R103 R104 R105 R106 R107 R108 R109 R110 R111 R112 R113 R118 R119 R120 R144 SW2 TP1 TP2 U20 U21 U22
component class CPU_MISC: C123 C124 C125 C126 J3 R147 R148 R149 R150 R151 R152 R153 R154 U12
component class CPU_IO: C143 D23 D24 R35 R39 R40 R41 R85 R86 R98 R99 R114 R115 R142 R143 R145 R146 S1 TP6 TP7 TP8 TP10 TP11 U28
component class "Mounting Holes": H1 H2 H3 H9 H11 H12
component class Logo: Logo1
component class HW: FID1 FID2 FID3 FID4 FID5 FID6 H1 H2 H3 H5 H6 H7 H9 H10 H11 H12 H13 H14 LBL1 Logo1 Logo2 Logo3 Logo4 TP3 TP4 TP5 ZZ1 ZZ2 ZZ3 ZZ4
component class FiducialMark: FID1 FID2 FID3 FID4 FID5 FID6
component class AssemblyNote: ZZ1 ZZ2 ZZ3 ZZ4
component class Label: LBL1
differential pair TD.2: +TD.2_P -TD.2_N
differential pair TD.1: +TD.1_P -TD.1_N
differential pair RD.2: +RD.2_P -RD.2_N
differential pair RD.1: +RD.1_P -RD.1_N
differential pair USB: +USB_P -USB_N

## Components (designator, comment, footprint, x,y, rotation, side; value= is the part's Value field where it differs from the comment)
C1.1 "885012208093" WCAP-CSGP_1206_L3.2W1.6H1.6 7240,800 r0 top value="1 µF" (schematic designator C1)
C1.2 "885012208093" WCAP-CSGP_1206_L3.2W1.6H1.6 7326.93,1562.2 r180 top value="1 µF" (schematic designator C1)
C1.3 "885012208093" WCAP-CSGP_1206_L3.2W1.6H1.6 6255.75,800 r0 top value="1 µF" (schematic designator C1)
C1.4 "885012208093" WCAP-CSGP_1206_L3.2W1.6H1.6 6342.68,1562.2 r180 top value="1 µF" (schematic designator C1)
C1.5 "885012208093" WCAP-CSGP_1206_L3.2W1.6H1.6 5358.43,1562.2 r180 top value="1 µF" (schematic designator C1)
C1.6 "885012208093" WCAP-CSGP_1206_L3.2W1.6H1.6 5271.5,800 r0 top value="1 µF" (schematic designator C1)
C1.7 "885012208093" WCAP-CSGP_1206_L3.2W1.6H1.6 4374.17,1562.2 r180 top value="1 µF" (schematic designator C1)
C1.8 "885012208093" WCAP-CSGP_1206_L3.2W1.6H1.6 4287.24,800 r0 top value="1 µF" (schematic designator C1)
C2.1 "885012206052" WCAP-CSGP_0603_L1.6W0.8H0.8_Reflow 7210,900 r180 top value="1 µF" (schematic designator C2)
C2.2 "885012206052" WCAP-CSGP_0603_L1.6W0.8H0.8_Reflow 7356.93,1462.2 r0 top value="1 µF" (schematic designator C2)
C2.3 "885012206052" WCAP-CSGP_0603_L1.6W0.8H0.8_Reflow 6225.75,900 r180 top value="1 µF" (schematic designator C2)
C2.4 "885012206052" WCAP-CSGP_0603_L1.6W0.8H0.8_Reflow 6372.68,1462.2 r0 top value="1 µF" (schematic designator C2)
C2.5 "885012206052" WCAP-CSGP_0603_L1.6W0.8H0.8_Reflow 5388.43,1462.2 r0 top value="1 µF" (schematic designator C2)
C2.6 "885012206052" WCAP-CSGP_0603_L1.6W0.8H0.8_Reflow 5241.5,900 r180 top value="1 µF" (schematic designator C2)
C2.7 "885012206052" WCAP-CSGP_0603_L1.6W0.8H0.8_Reflow 4404.17,1462.2 r0 top value="1 µF" (schematic designator C2)
C2.8 "885012206052" WCAP-CSGP_0603_L1.6W0.8H0.8_Reflow 4257.24,900 r180 top value="1 µF" (schematic designator C2)
C3 "885012105018" WCAP-CSGP_0402_L1W0.5H0.5 4170,1250 r0 top value="100 nF"
C4 "885012105018" WCAP-CSGP_0402_L1W0.5H0.5 5600,1290 r0 top value="100 nF"
C5 "885012105018" WCAP-CSGP_0402_L1W0.5H0.5 5800,1290 r0 top value="100 nF"
C6 "885012105018" WCAP-CSGP_0402_L1W0.5H0.5 6080,1280 r180 top value="100 nF"
C7 "885012105018" WCAP-CSGP_0402_L1W0.5H0.5 6260,1215 r90 bottom value="100 nF"
C8 "885012105018" WCAP-CSGP_0402_L1W0.5H0.5 5900,965 r0 bottom value="100 nF"
C9 "885012105018" WCAP-CSGP_0402_L1W0.5H0.5 5870,1375 r270 top value="100 nF"
C10 "885012105018" WCAP-CSGP_0402_L1W0.5H0.5 7365,1290 r270 bottom value="100 nF"
C11 "885012207124" WCAP-CSGP_0805_L2W1.25H0.8_Reflow 6560,1380 r180 top value="22 nF"
C12 "885012207124" WCAP-CSGP_0805_L2W1.25H0.8_Reflow 6560,980 r180 bottom value="22 nF"
C13 "885012207124" WCAP-CSGP_0805_L2W1.25H0.8_Reflow 7040,1380 r0 bottom value="22 nF"
C14 "885012207124" WCAP-CSGP_0805_L2W1.25H0.8_Reflow 7040,980 r0 top value="22 nF"
C15 "885012005080" FP-885012005080_0402-MFG 6820,1080 r270 top value=100pF
C16 "885012207124" WCAP-CSGP_0805_L2W1.25H0.8_Reflow 4590,980 r180 bottom value="22 nF"
C17 "885012207124" WCAP-CSGP_0805_L2W1.25H0.8_Reflow 4600,1380 r180 top value="22 nF"
C18 "885012207124" WCAP-CSGP_0805_L2W1.25H0.8_Reflow 5070,980 r0 top value="22 nF"
C19 "885012207124" WCAP-CSGP_0805_L2W1.25H0.8_Reflow 5060,1380 r0 bottom value="22 nF"
C20 "885012005080" FP-885012005080_0402-MFG 4780,1240 r90 bottom value=100pF
C21 "885012209071" WCAP-CSGP_1210_L3.2W2.5H2.5 6880,1195 r0 top value="2.2 µF"
C22 "885012209071" WCAP-CSGP_1210_L3.2W2.5H2.5 6720,1180 r180 top value="2.2 µF"
C23 "885012105018" WCAP-CSGP_0402_L1W0.5H0.5 4860,1230 r90 bottom value="100 nF"
C24 "885012105018" WCAP-CSGP_0402_L1W0.5H0.5 6860,1080 r270 top value="100 nF"
C25 "885012105012" 0402 3780,560 r180 bottom value=1uF
C26 "885012105012" 0402 3820,440 r0 bottom value=1uF
C27 "885012105012" 0402S 3677.81,542.5 r90 bottom value=1uF
C28 "885012105012" 0402 2260,760 r90 bottom value=1uF
C29 "885012105012" 0402 2420,670 r0 bottom value=1uF
C30 "885012105018" WCAP-CSGP_0402_L1W0.5H0.5 3890,690 r0 bottom value="100 nF"
C31 "885012205012" WCAP-CSGP_0402_L1W0.5H0.5 1950,270 r90 top value="10 nF"
C32 "885012105012" 0402 2385,825 r180 bottom value=1uF
C33 "885012105018" WCAP-CSGP_0402_L1W0.5H0.5 2260,950 r0 bottom value="100 nF"
C34 "885012105018" WCAP-CSGP_0402_L1W0.5H0.5 2080,150 r270 bottom value="100 nF"
C35 "885012105012" 0402 1720,130 r90 bottom value=1uF
C36 "885012105018" WCAP-CSGP_0402_L1W0.5H0.5 2020,180 r0 bottom value="100 nF"
C37 "885012105018" WCAP-CSGP_0402_L1W0.5H0.5 3390,860 r270 top value="100 nF"
C38 "885012105018" WCAP-CSGP_0402_L1W0.5H0.5 1810,180 r0 top value="100 nF"
C39 "885012105012" 0402 1720,380 r0 bottom value=1uF
C41 "885012105012" 0402 1770,300 r90 bottom value=1uF
C42 "885012105012" 0402 1840,350 r180 bottom value=1uF
C43 "885012105012" 0402 1840,390 r180 bottom value=1uF
C44 "885012106005" WCAP-CSGP_0603_L1.6W0.8H0.8_Reflow 2770,385 r0 bottom value="4.7 µF"
C45 "885012106005" WCAP-CSGP_0603_L1.6W0.8H0.8_Reflow 3025,595 r180 bottom value="4.7 µF"
C46 "885012106005" WCAP-CSGP_0603_L1.6W0.8H0.8_Reflow 2990,515 r270 bottom value="4.7 µF"
C47 "885012104009" WCAP-CSGP_0201_L0.6W0.3H0.3 3150,420 r315 bottom value=100nF
C48 "885012104009" WCAP-CSGP_0201_L0.6W0.3H0.3 2955,405 r225 bottom value=100nF
C49 "885012104009" WCAP-CSGP_0201_L0.6W0.3H0.3 2990,340 r135 bottom value=100nF
C50 "885012104009" WCAP-CSGP_0201_L0.6W0.3H0.3 3020,395 r270 bottom value=100nF
C51 "885012104009" WCAP-CSGP_0201_L0.6W0.3H0.3 3125,400 r315 bottom value=100nF
C52 "885012104009" WCAP-CSGP_0201_L0.6W0.3H0.3 2950,460 r180 bottom value=100nF
C53 "885012104009" WCAP-CSGP_0201_L0.6W0.3H0.3 2950,540 r180 bottom value=100nF
C54 "885012104009" WCAP-CSGP_0201_L0.6W0.3H0.3 2925,490 r225 bottom value=100nF
C55 "885012104009" WCAP-CSGP_0201_L0.6W0.3H0.3 3150,525 r45 bottom value=100nF
C56 "885012104009" WCAP-CSGP_0201_L0.6W0.3H0.3 3060,390 r315 bottom value=100nF
C57 "885012104009" WCAP-CSGP_0201_L0.6W0.3H0.3 2950,575 r135 bottom value=100nF
C58 "885012104009" WCAP-CSGP_0201_L0.6W0.3H0.3 3230,445 r180 bottom value=100nF
C59 "885012104009" WCAP-CSGP_0201_L0.6W0.3H0.3 3145,595 r45 bottom value=100nF
C60 "885012104009" WCAP-CSGP_0201_L0.6W0.3H0.3 2980,400 r225 bottom value=100nF
C61 "885012106005" WCAP-CSGP_0603_L1.6W0.8H0.8_Reflow 2770,435 r0 bottom value="4.7 µF"
C62 "885012104009" WCAP-CSGP_0201_L0.6W0.3H0.3 2925,595 r270 bottom value=100nF
C63 "885012106005" WCAP-CSGP_0603_L1.6W0.8H0.8_Reflow 2770,475 r0 bottom value="4.7 µF"
C64 "885012104009" WCAP-CSGP_0201_L0.6W0.3H0.3 3155,570 r45 bottom value=100nF
C65 "885012106005" WCAP-CSGP_0603_L1.6W0.8H0.8_Reflow 3240,680 r270 bottom value="4.7 µF"
C66 "885012106005" WCAP-CSGP_0603_L1.6W0.8H0.8_Reflow 3165,730 r270 bottom value="4.7 µF"
C67 "885012104009" WCAP-CSGP_0201_L0.6W0.3H0.3 2955,370 r315 bottom value=100nF
C68 "885012104009" WCAP-CSGP_0201_L0.6W0.3H0.3 2920,420 r180 bottom value=100nF
C69 "885012104009" WCAP-CSGP_0201_L0.6W0.3H0.3 3230,425 r180 bottom value=100nF
C70 "885012104009" WCAP-CSGP_0201_L0.6W0.3H0.3 3085,350 r270 bottom value=100nF
C71 "885012104009" WCAP-CSGP_0201_L0.6W0.3H0.3 3190,570 r0 bottom value=100nF
C72 "885012104009" WCAP-CSGP_0201_L0.6W0.3H0.3 3170,650 r90 bottom value=100nF
C73 "885012104009" WCAP-CSGP_0201_L0.6W0.3H0.3 2925,635 r135 bottom value=100nF
C74 "885012104009" WCAP-CSGP_0201_L0.6W0.3H0.3 2895,515 r180 bottom value=100nF
C75 "885012106005" WCAP-CSGP_0603_L1.6W0.8H0.8_Reflow 3085,700 r270 bottom value="4.7 µF"
C76 "885012104009" WCAP-CSGP_0201_L0.6W0.3H0.3 2905,680 r270 bottom value=100nF
C77 "885012104009" WCAP-CSGP_0201_L0.6W0.3H0.3 3055,700 r270 bottom value=100nF
C78 "885012104009" WCAP-CSGP_0201_L0.6W0.3H0.3 3190,665 r270 bottom value=100nF
C79 "885012104009" WCAP-CSGP_0201_L0.6W0.3H0.3 3138.66,665 r180 bottom value=100nF
C80 "885012104009" WCAP-CSGP_0201_L0.6W0.3H0.3 3125,725 r270 bottom value=100nF
C81 "885012104009" WCAP-CSGP_0201_L0.6W0.3H0.3 3205,730 r0 bottom value=100nF
C82 "885012104009" WCAP-CSGP_0201_L0.6W0.3H0.3 3225,600 r315 bottom value=100nF
C83 "885012104009" WCAP-CSGP_0201_L0.6W0.3H0.3 3130,625 r45 bottom value=100nF
C84 "885012106005" WCAP-CSGP_0603_L1.6W0.8H0.8_Reflow 2875,640 r270 bottom value="4.7 µF"
C85 "885012104009" WCAP-CSGP_0201_L0.6W0.3H0.3 2900,565 r270 bottom value=100nF
C86 "885012106005" WCAP-CSGP_0603_L1.6W0.8H0.8_Reflow 3175,475 r0 bottom value="4.7 µF"
C87 "885012104009" WCAP-CSGP_0201_L0.6W0.3H0.3 3160,445 r0 bottom value=100nF
C88 "885012104009" WCAP-CSGP_0201_L0.6W0.3H0.3 2960,630 r90 bottom value=100nF
C89 "885012104009" WCAP-CSGP_0201_L0.6W0.3H0.3 3170,515 r45 bottom value=100nF
C90 "885012104009" WCAP-CSGP_0201_L0.6W0.3H0.3 3180,600 r315 bottom value=100nF
C91 "885012106005" WCAP-CSGP_0603_L1.6W0.8H0.8_Reflow 2895,310 r0 bottom value="4.7 µF"
C92 "885012106005" WCAP-CSGP_0603_L1.6W0.8H0.8_Reflow 3145,285 r90 bottom value="4.7 µF"
C93 "885012106005" WCAP-CSGP_0603_L1.6W0.8H0.8_Reflow 3210,285 r90 bottom value="4.7 µF"
C94 "885012104009" WCAP-CSGP_0201_L0.6W0.3H0.3 2920,375 r225 bottom value=100nF
C95 "885012104009" WCAP-CSGP_0201_L0.6W0.3H0.3 2920,440 r180 bottom value=100nF
C96 "885012104009" WCAP-CSGP_0201_L0.6W0.3H0.3 2930,520 r180 bottom value=100nF
C97 "885012104009" WCAP-CSGP_0201_L0.6W0.3H0.3 3040,360 r270 bottom value=100nF
C98 "885012104009" WCAP-CSGP_0201_L0.6W0.3H0.3 3163.88,363.88 r225 bottom value=100nF
C99 "885012104009" WCAP-CSGP_0201_L0.6W0.3H0.3 3180,400 r45 bottom value=100nF
C100 "885012106005" WCAP-CSGP_0603_L1.6W0.8H0.8_Reflow 3040,765 r270 bottom value="4.7 µF"
C101 "885012104009" WCAP-CSGP_0201_L0.6W0.3H0.3 3105,635 r90 bottom value=100nF
C102 "885012104009" WCAP-CSGP_0201_L0.6W0.3H0.3 2995,635 r90 bottom value=100nF
C103 "885012105018" WCAP-CSGP_0402_L1W0.5H0.5 2150,1230 r180 bottom value="100 nF"
C104 "885012209048" FP-885012209048_1210-MFG 2260,1170 r270 bottom value=4.7µF
C105 "885012209048" FP-885012209048_1210-MFG 2260,1170 r270 top value=4.7µF
C106 "885012209048" FP-885012209048_1210-MFG 2380,1170 r270 top value=4.7µF
C107 "885012209048" FP-885012209048_1210-MFG 2380,1170 r270 bottom value=4.7µF
C108 "885012208019" 1206_190 2380,1350 r270 bottom value=22uF
C109 "885012208019" 1206_190 2290,1350 r270 bottom value=22uF
C110 "885012208041" 1206 2380,1350 r270 top value=10uF
C111 "885012208041" 1206 2290,1350 r270 top value=10uF
C112 "885392005116" WCAP-CSRF_0402_L1W0.5H0.5 2030,1120 r270 top value=27pF
C113 "885012208041" 1206 1840,1220 r180 top value=10uF
C114 "885392005116" WCAP-CSRF_0402_L1W0.5H0.5 1900,1330 r270 bottom value=27pF
C115 "885012208019" 1206_190 1840,1130 r180 top value=22uF
C116 "865230557007" WCAP-AS5H_D10H10.5 2660,1450 r270 top value="220 µF"
C117 "885012105018" WCAP-CSGP_0402_L1W0.5H0.5 3550,1440 r90 bottom value="100 nF"
C118 "885012208087" WCAP-CSGP_1206_L3.2W1.6H0.8 3540,1570 r270 bottom value="100 nF"
C119 "GRM1555C1E270JA01D" 0402S 3390,1570 r180 bottom value=27pF
C120 "885012209048" FP-885012209048_1210-MFG 3340,1710 r180 bottom value=4.7µF
C121 "885012106005" WCAP-CSGP_0603_L1.6W0.8H0.8_Reflow 3205,825 r270 top value="4.7 µF"
C122 "885012104009" WCAP-CSGP_0201_L0.6W0.3H0.3 3025,700 r270 bottom value=100nF
C123 "885012106005" WCAP-CSGP_0603_L1.6W0.8H0.8_Reflow 3095,830 r0 top value="4.7 µF"
C124 "885012104009" WCAP-CSGP_0201_L0.6W0.3H0.3 3105,790 r0 top value=100nF
C125 "885012106005" WCAP-CSGP_0603_L1.6W0.8H0.8_Reflow 2990,830 r0 top value="4.7 µF"
C126 "885012104009" WCAP-CSGP_0201_L0.6W0.3H0.3 3000,790 r0 top value=100nF
C127.1 "GRM1555C1H4R7WA01D" 0402 1060,1840 r270 top value=4.7pF (schematic designator C127)
C127.2 "GRM1555C1H4R7WA01D" 0402 1060,658.9 r270 top value=4.7pF (schematic designator C127)
C128.1 "885012205063" WCAP-CSGP_0402_L1W0.5H0.5 990,1720 r0 bottom value=2.2nF (schematic designator C128)
C128.2 "885012205063" WCAP-CSGP_0402_L1W0.5H0.5 990,538.9 r0 bottom value=2.2nF (schematic designator C128)
C129.1 "885012208041" 1206 1070,1620 r0 top value=10uF (schematic designator C129)
C129.2 "885012208041" 1206 1070,438.9 r0 top value=10uF (schematic designator C129)
C130.1 "885012105012" 0402 1100,1690 r0 top value=1uF (schematic designator C130)
C130.2 "885012105012" 0402 1100,508.9 r0 top value=1uF (schematic designator C130)
C131.1 "885012205012" WCAP-CSGP_0402_L1W0.5H0.5 1100,1750 r180 top value="10 nF" (schematic designator C131)
C131.2 "885012205012" WCAP-CSGP_0402_L1W0.5H0.5 1100,568.9 r180 top value="10 nF" (schematic designator C131)
C132.1 "885012208041" 1206 1200,1940 r180 top value=10uF (schematic designator C132)
C132.2 "885012208041" 1206 1200,758.9 r180 top value=10uF (schematic designator C132)
C133.1 "885012105012" 0402 1200,1880 r180 top value=1uF (schematic designator C133)
C133.2 "885012105012" 0402 1200,698.9 r180 top value=1uF (schematic designator C133)
C134.1 "885012205012" WCAP-CSGP_0402_L1W0.5H0.5 1200,1850 r0 top value="10 nF" (schematic designator C134)
C134.2 "885012205012" WCAP-CSGP_0402_L1W0.5H0.5 1200,668.9 r0 top value="10 nF" (schematic designator C134)
C135.1 "885012105018" WCAP-CSGP_0402_L1W0.5H0.5 1100,1720 r180 top value="100 nF" (schematic designator C135)
C135.2 "885012105018" WCAP-CSGP_0402_L1W0.5H0.5 1100,538.9 r180 top value="100 nF" (schematic designator C135)
C136.1 "885012105012" 0402 800,1830 r180 bottom value=1uF (schematic designator C136)
C136.2 "885012105012" 0402 800,650 r180 bottom value=1uF (schematic designator C136)
C137.1 "885012105018" WCAP-CSGP_0402_L1W0.5H0.5 1200,1820 r0 top value="100 nF" (schematic designator C137)
C137.2 "885012105018" WCAP-CSGP_0402_L1W0.5H0.5 1200,638.9 r0 top value="100 nF" (schematic designator C137)
C138.1 "885012105012" 0402 800,1670 r180 bottom value=1uF (schematic designator C138)
C138.2 "885012105012" 0402 800,490 r180 bottom value=1uF (schematic designator C138)
C139.1 "885012105018" WCAP-CSGP_0402_L1W0.5H0.5 800,1870 r0 bottom value="100 nF" (schematic designator C139)
C139.2 "885012105018" WCAP-CSGP_0402_L1W0.5H0.5 800,690 r0 bottom value="100 nF" (schematic designator C139)
C140.1 "1825GC103KAT1A" 1825 520,1771.65 r180 bottom value=0.01uF (schematic designator C140)
C140.2 "1825GC103KAT1A" 1825 520,590 r180 bottom value=0.01uF (schematic designator C140)
C141.1 "885012105018" WCAP-CSGP_0402_L1W0.5H0.5 800,1710 r0 bottom value="100 nF" (schematic designator C141)
C141.2 "885012105018" WCAP-CSGP_0402_L1W0.5H0.5 800,530 r0 bottom value="100 nF" (schematic designator C141)
C142.1 "885012105018" WCAP-CSGP_0402_L1W0.5H0.5 1170,1490 r270 bottom value="100 nF" (schematic designator C142)
C142.2 "885012105018" WCAP-CSGP_0402_L1W0.5H0.5 1170,308.9 r270 bottom value="100 nF" (schematic designator C142)
C143 "885012105018" WCAP-CSGP_0402_L1W0.5H0.5 2950,60 r180 bottom value="100 nF"
C144 "885012105012" 0402 2515,1930 r270 top value=1uF
C145 "885012205012" WCAP-CSGP_0402_L1W0.5H0.5 2625,1930 r90 bottom value="10 nF"
C146 "885012105012" 0402 2575,1930 r270 top value=1uF
C147 "885012205012" WCAP-CSGP_0402_L1W0.5H0.5 2190,2215 r270 top value="10 nF"
C148 "885012209071" WCAP-CSGP_1210_L3.2W2.5H2.5 4760,1140 r180 bottom value="2.2 µF"
C149 "885012105018" WCAP-CSGP_0402_L1W0.5H0.5 2065,2025 r90 top value="100 nF"
C150 "885012105018" WCAP-CSGP_0402_L1W0.5H0.5 1900,2170 r180 bottom value="100 nF"
C151 "885012105018" WCAP-CSGP_0402_L1W0.5H0.5 2030,1580 r0 top value="100 nF"
C152 "885012105018" WCAP-CSGP_0402_L1W0.5H0.5 1750,1605 r270 top value="100 nF"
C153 "885012105018" WCAP-CSGP_0402_L1W0.5H0.5 1690,1800 r270 top value="100 nF"
C154 "885012105012" 0402 2095,2025 r270 top value=1uF
C155 "885012105012" 0402 2130,1855 r180 top value=1uF
C156 "885012205012" WCAP-CSGP_0402_L1W0.5H0.5 2130,1825 r0 top value="10 nF"
C157 "885012105018" WCAP-CSGP_0402_L1W0.5H0.5 2130,1795 r0 top value="100 nF"
C158 "885012105012" 0402 2020,2025 r270 top value=1uF
C159 "885012105012" 0402 2130,1765 r180 top value=1uF
C160 "885392005127" FP-885392005127_0402-MFG 2000,2220 r90 top value=12pF
C161 "885392005127" FP-885392005127_0402-MFG 2080,2220 r270 top value=12pF
C162 "885012105018" WCAP-CSGP_0402_L1W0.5H0.5 1675,2220 r270 bottom value="100 nF"
C163 "885012209071" WCAP-CSGP_1210_L3.2W2.5H2.5 4920,1140 r0 bottom value="2.2 µF"
C164 "885012105012" 0402 1840,315 r180 bottom value=1uF
D1 "150066RG74000" FP-150066RG74000_0606-MFG 7283.46,98.43 r0 top value=Red/Green
D2 "150066RG74000" FP-150066RG74000_0606-MFG 7283.46,2263.78 r0 top value=Red/Green
D3 "150066RG74000" FP-150066RG74000_0606-MFG 6299.21,98.43 r0 top value=Red/Green
D4 "150066RG74000" FP-150066RG74000_0606-MFG 6299.21,2263.78 r0 top value=Red/Green
D5 "150066RG74000" FP-150066RG74000_0606-MFG 5314.96,98.43 r0 top value=Red/Green
D6 "150066RG74000" FP-150066RG74000_0606-MFG 5314.96,2263.78 r0 top value=Red/Green
D7 "150066RG74000" FP-150066RG74000_0606-MFG 4330.71,98.43 r0 top value=Red/Green
D8 "150066RG74000" FP-150066RG74000_0606-MFG 4330.71,2263.78 r0 top value=Red/Green
D9 "150040GS73240" WL-SMCC_0402_Green 7086.61,98.43 r90 top value=Green
D10 "150040GS73240" WL-SMCC_0402_Green 7086.61,2263.78 r90 top value=Green
D11 "150040GS73240" WL-SMCC_0402_Green 6102.36,98.43 r90 top value=Green
D12 "150040GS73240" WL-SMCC_0402_Green 6102.36,2263.78 r90 top value=Green
D13 "150040GS73240" WL-SMCC_0402_Green 5118.11,98.43 r90 top value=Green
D14 "150040GS73240" WL-SMCC_0402_Green 5118.11,2263.78 r90 top value=Green
D15 "150040GS73240" WL-SMCC_0402_Green 4133.86,98.43 r90 top value=Green
D16 "150040GS73240" WL-SMCC_0402_Green 4133.86,2263.78 r90 top value=Green
D20 "150040GS73240" WL-SMCC_0402_Green 2800,1700 r180 top value=Green
D21 "150040GS73240" WL-SMCC_0402_Green 2330,1490 r90 top value=Green
D22 "150040GS73240" WL-SMCC_0402_Green 1990,1040 r270 top value=Green
D23 "150040RS73240" FP-150040RS73220_0402-MFG 3250,100 r270 top
D24 "150040GS73240" WL-SMCC_0402_Green 3200,100 r270 top value=Green
D25 "SMCJ33CA" SMC_Bi 3550,1900 r180 bottom value=33V
D26.1 "ESD441DPLR" DPL0002A-MFG 960,2000 r90 top (schematic designator D26)
D26.2 "ESD441DPLR" DPL0002A-MFG 960,818.9 r90 top (schematic designator D26)
D27.1 "ESD441DPLR" DPL0002A-MFG 960,1590 r270 top (schematic designator D27)
D27.2 "ESD441DPLR" DPL0002A-MFG 960,408.9 r270 top (schematic designator D27)
D28 "150040RS73240" FP-150040RS73220_0402-MFG 2135,1605 r270 top
D29 "150040GS73240" WL-SMCC_0402_Green 2090,1605 r270 top value=Green
D30 "150040GS73240" WL-SMCC_0402_Green 1920,1605 r270 top value=Green
D31 "150040GS73240" WL-SMCC_0402_Green 2549.96,2000 r180 top value=Green
D35 "TPD2E2U06DCKR" DCK0003A-MFG 2480,2210 r90 bottom
F1 "TR2/6125FF10-R" FUSE_6125FF 3030,1700 r90 bottom value=10A
FID1 "Fiducial" Fiducial10-20 150,2250 r0 top
FID2 "Fiducial" Fiducial10-20 150,100 r0 top
FID3 "Fiducial" Fiducial10-20 7700,1430 r0 top
FID4 "Fiducial" Fiducial10-20 7800,1800 r180 bottom
FID5 "Fiducial" Fiducial10-20 150,100 r180 bottom
FID6 "Fiducial" Fiducial10-20 150,2250 r180 bottom
H1 "NY PMS 440 0025 PH" "NY PMS 440 0025 PH" 1181.1,2165.35 r0 top
H2 "NY PMS 440 0025 PH" "NY PMS 440 0025 PH" 196.85,1181.1 r0 top
H3 "NY PMS 440 0025 PH" "NY PMS 440 0025 PH" 7677.17,1181.1 r0 top
H5 "1902C" Keystone_1902C 1181.1,2165.35 r180 bottom
H6 "1902C" Keystone_1902C 196.85,1181.1 r180 bottom
H7 "1902C" Keystone_1902C 7677.17,1181.1 r180 bottom
H9 "NY PMS 440 0025 PH" "NY PMS 440 0025 PH" 1377.95,196.85 r0 top
H10 "1902C" Keystone_1902C 1377.95,196.85 r180 bottom
H11 "NY PMS 440 0025 PH" "NY PMS 440 0025 PH" 7677.17,196.85 r0 top
H12 "NY PMS 440 0025 PH" "NY PMS 440 0025 PH" 7677.17,2165.35 r0 top
H13 "1902C" Keystone_1902C 7677.52,196.85 r180 bottom
H14 "1902C" Keystone_1902C 7677.52,2165.35 r180 bottom
J1.1 "643260100605" 643260100605 7283.46,590.55 r0 top locked (schematic designator J1)
J1.2 "643260100605" 643260100605 7283.46,1771.65 r180 top locked (schematic designator J1)
J1.3 "643260100605" 643260100605 6299.21,590.55 r0 top locked (schematic designator J1)
J1.4 "643260100605" 643260100605 6299.21,1771.65 r180 top locked (schematic designator J1)
J1.5 "643260100605" 643260100605 5314.96,1771.65 r180 top locked (schematic designator J1)
J1.6 "643260100605" 643260100605 5314.96,590.55 r0 top locked (schematic designator J1)
J1.7 "643260100605" 643260100605 4330.71,1771.65 r180 top locked (schematic designator J1)
J1.8 "643260100605" 643260100605 4330.71,590.55 r0 top locked (schematic designator J1)
J2 "694106301002" FP-694106301002_CONN_PWR_JACK-MFG 3031.5,2187.01 r180 top
J3 "FTR-110-51-S-D-06" Samtec_FTR-110-51-x-D-06 1550,1120 r180 top
J4.1 "7498011211" 7498011211 433.07,1771.65 r270 top (schematic designator J4)
J4.2 "7498011211" 7498011211 433.07,590.55 r270 top locked (schematic designator J4)
J5 "691305540002" 691305540002 3543.31,2244.09 r180 top
J6 "SPI Debug Header" WURTH_61300411121 2350,1850 r270 top
J7 "629105150521" FP-629105150521_CONN_USB_8MM0_6MM6-MFG 2460,2125 r180 top
J8 "61300311121" WURTH_61300311121 3700,300 r180 top
J9 "61300311121" WURTH_61300311121 3700,205 r180 top
L1 "7427927291" 0402 1890,450 r0 bottom value="600 ohm"
L2 "74279271" 0402 3165,825 r90 top value="120 ohm"
L3 "74279271" 0402 3050,635 r180 bottom value="120 ohm"
L4 "74438367068" WE-MAPI_5030 2120,1380 r90 top value="6.8 µH"
L5 "74438336010" WE-MAPI_3020 1850,1190 r270 bottom value="1 µH"
L6 "7448031002" FP-7448031002_PTH4_23MM0_17MM0-MFG 3350,1550 r180 top
L7.1 "7427927291" 0402 1100,1550 r0 top value="600 ohm" (schematic designator L7)
L7.2 "7427927291" 0402 1100,368.9 r0 top value="600 ohm" (schematic designator L7)
L8.1 "7427927291" 0402 1320,1940 r270 top value="600 ohm" (schematic designator L8)
L8.2 "7427927291" 0402 1320,758.9 r270 top value="600 ohm" (schematic designator L8)
L9 "7427927291" 0402 1945,315 r0 bottom value="600 ohm"
LBL1 "THT-14-423-10" Label_650x200 4740,210 r180 bottom
Logo1 "Texas Instruments" TI_Stacked_Overlay_Small 3360,1090 r0 top
Logo2 "CE Mark" CE_Mark_5mm 4820,1970 r0 bottom
Logo3 "FCC disclaimer" FCC_disclaimer 4935,2135 r180 bottom
Logo4 "WEEE logo" WEEE_Minimum 4830,1730 r180 bottom
Q1 "CSD18543Q3A" DNH0008A#1 7039.61,1090 r0 top value=60V
Q2 "CSD18543Q3A" DNH0008A#2 7040,1270 r0 bottom value=60V
Q3 "CSD18543Q3A" DNH0008A#2 6550,1090 r180 bottom value=60V
Q4 "CSD18543Q3A" DNH0008A#1 6550,1270 r180 top value=60V
Q5 "CSD18543Q3A" DNH0008A#2 5070,1270 r0 bottom value=60V
Q6 "CSD18543Q3A" DNH0008A#1 5070,1090 r0 top value=60V
Q7 "CSD18543Q3A" DNH0008A#1 4590,1270 r180 top value=60V
Q8 "CSD18543Q3A" DNH0008A#2 4590,1090 r180 bottom value=60V
Q9 "CSD18531Q5A" DQJ0008A 3350,1365.04 r270 bottom value=60V
Q10 "CSD18531Q5A" DQJ0008A 3055,1359.96 r270 bottom value=60V
Q11 "BC847BW,115" SOT-323 1940,1040 r0 bottom value="45 V"
R1.1 "CRCW04020000Z0EDC" FP-CRCW04020000Z0EDC_0402-IPC_A 7420,890 r180 bottom value=0 (schematic designator R1)
R1.2 "CRCW04020000Z0EDC" FP-CRCW04020000Z0EDC_0402-IPC_A 7146.93,1472.2 r0 bottom value=0 (schematic designator R1)
R1.3 "CRCW04020000Z0EDC" FP-CRCW04020000Z0EDC_0402-IPC_A 6435.75,890 r180 bottom value=0 (schematic designator R1)
R1.4 "CRCW04020000Z0EDC" FP-CRCW04020000Z0EDC_0402-IPC_A 6162.68,1472.2 r0 bottom value=0 (schematic designator R1)
R1.5 "CRCW04020000Z0EDC" FP-CRCW04020000Z0EDC_0402-IPC_A 5178.43,1472.2 r0 bottom value=0 (schematic designator R1)
R1.6 "CRCW04020000Z0EDC" FP-CRCW04020000Z0EDC_0402-IPC_A 5451.5,890 r180 bottom value=0 (schematic designator R1)
R1.7 "CRCW04020000Z0EDC" FP-CRCW04020000Z0EDC_0402-IPC_A 4194.17,1472.2 r0 bottom value=0 (schematic designator R1)
R1.8 "CRCW04020000Z0EDC" FP-CRCW04020000Z0EDC_0402-IPC_A 4467.24,890 r180 bottom value=0 (schematic designator R1)
R2.1 "CRCW040210K0JNED" 0402 7420,850 r180 bottom value=10k (schematic designator R2)
R2.2 "CRCW040210K0JNED" 0402 7146.93,1512.2 r0 bottom value=10k (schematic designator R2)
R2.3 "CRCW040210K0JNED" 0402 6435.75,850 r180 bottom value=10k (schematic designator R2)
R2.4 "CRCW040210K0JNED" 0402 6162.68,1512.2 r0 bottom value=10k (schematic designator R2)
R2.5 "CRCW040210K0JNED" 0402 5178.43,1512.2 r0 bottom value=10k (schematic designator R2)
R2.6 "CRCW040210K0JNED" 0402 5451.5,850 r180 bottom value=10k (schematic designator R2)
R2.7 "CRCW040210K0JNED" 0402 4194.17,1512.2 r0 bottom value=10k (schematic designator R2)
R2.8 "CRCW040210K0JNED" 0402 4467.24,850 r180 bottom value=10k (schematic designator R2)
R3 "CRCW04021K00FKED" 0402 7380,70 r0 top value=1.00k
R4 "CRCW04021K00FKED" 0402 7380,120 r0 top value=1.00k
R5 "CRCW04021K00FKED" 0402 7380,2240 r0 top value=1.00k
R6 "CRCW04021K00FKED" 0402 7380,2290 r0 top value=1.00k
R7 "CRCW04021K00FKED" 0402 6400,70 r0 top value=1.00k
R8 "CRCW04021K00FKED" 0402 6400,120 r0 top value=1.00k
R9 "CRCW04021K00FKED" 0402 6400,2240 r0 top value=1.00k
R10 "CRCW04021K00FKED" 0402 6400,2290 r0 top value=1.00k
R11 "CRCW04021K00FKED" 0402 5410,70 r0 top value=1.00k
R12 "CRCW04021K00FKED" 0402 5410,120 r0 top value=1.00k
R13 "CRCW04021K00FKED" 0402 5420,2240 r0 top value=1.00k
R14 "CRCW04021K00FKED" 0402 5420,2290 r0 top value=1.00k
R15 "CRCW04021K00FKED" 0402 4430,70 r0 top value=1.00k
R16 "CRCW04021K00FKED" 0402 4430,120 r0 top value=1.00k
R17 "CRCW04021K00FKED" 0402 4430,2240 r0 top value=1.00k
R18 "CRCW04021K00FKED" 0402 4430,2290 r0 top value=1.00k
R19 "CRCW04023K30JNED" 0402 7130,100 r270 top value=3.3k
R20 "CRCW04023K30JNED" 0402 7130,2260 r270 top value=3.3k
R21 "CRCW04023K30JNED" 0402 6150,100 r270 top value=3.3k
R22 "CRCW04023K30JNED" 0402 6150,2260 r270 top value=3.3k
R23 "CRCW04023K30JNED" 0402 5170,100 r270 top value=3.3k
R24 "CRCW04023K30JNED" 0402 5160,2260 r270 top value=3.3k
R25 "CRCW04023K30JNED" 0402 4170,100 r270 top value=3.3k
R26 "CRCW04023K30JNED" 0402 4180,2260 r270 top value=3.3k
R27 "CRCW04020000Z0EDC" FP-CRCW04020000Z0EDC_0402-MFG 6815,1320 r0 bottom value=0
R28 "CRCW04020000Z0EDC" FP-CRCW04020000Z0EDC_0402-MFG 6840,1010 r180 bottom value=0
R29 "CRCW040210K0JNED" 0402 4920,1320 r90 top value=10k
R30 "CRCW04020000Z0EDC" FP-CRCW04020000Z0EDC_0402-MFG 6860,1290 r270 top value=0
R31 "CRCW040213K3FKED" 0402 6900,1290 r90 top value=13.3k
R32 "CRCW04021K00FKED" 0402 6780,1080 r270 top value=1.00k
R33 "CRCW04020000Z0EDC" FP-CRCW04020000Z0EDC_0402-MFG 4845,975 r0 top value=0
R34 "CRCW04020000Z0EDC" FP-CRCW04020000Z0EDC_0402-MFG 4880,1320 r90 top value=0
R35 "CRCW04020000Z0EDC" FP-CRCW04020000Z0EDC_0402-MFG 3095,200 r180 top value=0
R36 "CRCW04021K00FKED" 0402 4820,1240 r90 bottom value=1.00k
R37 "CRCW04020000Z0EDC" FP-CRCW04020000Z0EDC_0402-MFG 4900,1020 r90 bottom value=0
R38 "CRCW040223K7FKED" 0402 4940,1020 r270 bottom value=23.7k
R39 "CRCW040233R0JNED" 0402 2910,195 r0 top value=33
R40 "CRCW040233R0JNED" 0402 2810,195 r0 top value=33
R41 "CRCW04022K20JNED" 0402 1210,1020 r180 top value=2.2k
R42 "CRCW040210K0JNED" 0402S 3805,680 r90 bottom value=10k
R43 "CRCW040210K0JNED" 0402S 3625,530 r270 bottom value=10k
R44 "RC0201FR-7D49K9L" 0201L 3565,465 r0 bottom value=49.9k
R45 "RC0201FR-7D49K9L" 0201L 3565,540 r0 bottom value=49.9k
R46 "RC0201JR-7D4K7L" 0201L 3565,640 r0 bottom value=4.7k
R47 "RC0201FR-7D49K9L" 0201L 3565,490 r0 bottom value=49.9k
R48 "RC0201FR-7D49K9L" 0201L 3565,690 r0 bottom value=49.9k
R49 "RC0201FR-7D49K9L" 0201L 3565,440 r0 bottom value=49.9k
R50 "RC0201FR-7D49K9L" 0201L 3565,665 r0 bottom value=49.9k
R51 "RC0201FR-7D49K9L" 0201L 3565,515 r0 bottom value=49.9k
R52 "RC0201JR-7D22RL" 0201L 3565,595 r0 top value=22
R53 "RC0201JR-7D22RL" 0201L 3565,470 r0 top value=22
R54 "RC0201JR-7D22RL" 0201L 3565,545 r0 top value=22
R55 "RC0201JR-7D22RL" 0201L 3565,620 r0 top value=22
R56 "RC0201JR-7D22RL" 0201L 3565,495 r0 top value=22
R57 "RC0201JR-7D22RL" 0201L 3565,670 r0 top value=22
R58 "RC0201JR-7D22RL" 0201L 3565,445 r0 top value=22
R59 "RC0201JR-7D22RL" 0201L 3565,645 r0 top value=22
R60 "RC0201JR-7D22RL" 0201L 3565,520 r0 top value=22
R61 "CRCW04021K00FKED" 0402S 3565,610 r180 bottom value=1.00k
R62 "RC0402FR-07100KL" 0402S 3565,575 r0 bottom value=100k
R63 "CRCW040210K0JNED" 0402S 2565,710 r180 bottom value=10k
R64 "CRCW040210K0JNED" 0402S 2565,845 r180 bottom value=10k
R65 "RC0201FR-7D49K9L" 0201L 2615,695 r180 bottom value=49.9k
R66 "RC0201FR-7D49K9L" 0201L 2615,845 r180 bottom value=49.9k
R67 "RC0201JR-7D4K7L" 0201L 2615,820 r180 bottom value=4.7k
R68 "RC0201FR-7D49K9L" 0201L 2615,795 r180 bottom value=49.9k
R69 "RC0201FR-7D49K9L" 0201L 2615,745 r180 bottom value=49.9k
R70 "RC0201FR-7D49K9L" 0201L 2615,670 r180 bottom value=49.9k
R71 "RC0201FR-7D49K9L" 0201L 2615,620 r180 bottom value=49.9k
R72 "RC0201FR-7D49K9L" 0201L 2615,720 r180 bottom value=49.9k
R73 "CRCW04020000Z0EDC" FP-CRCW04020000Z0EDC_0402-MFG 2565,710 r180 top value=0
